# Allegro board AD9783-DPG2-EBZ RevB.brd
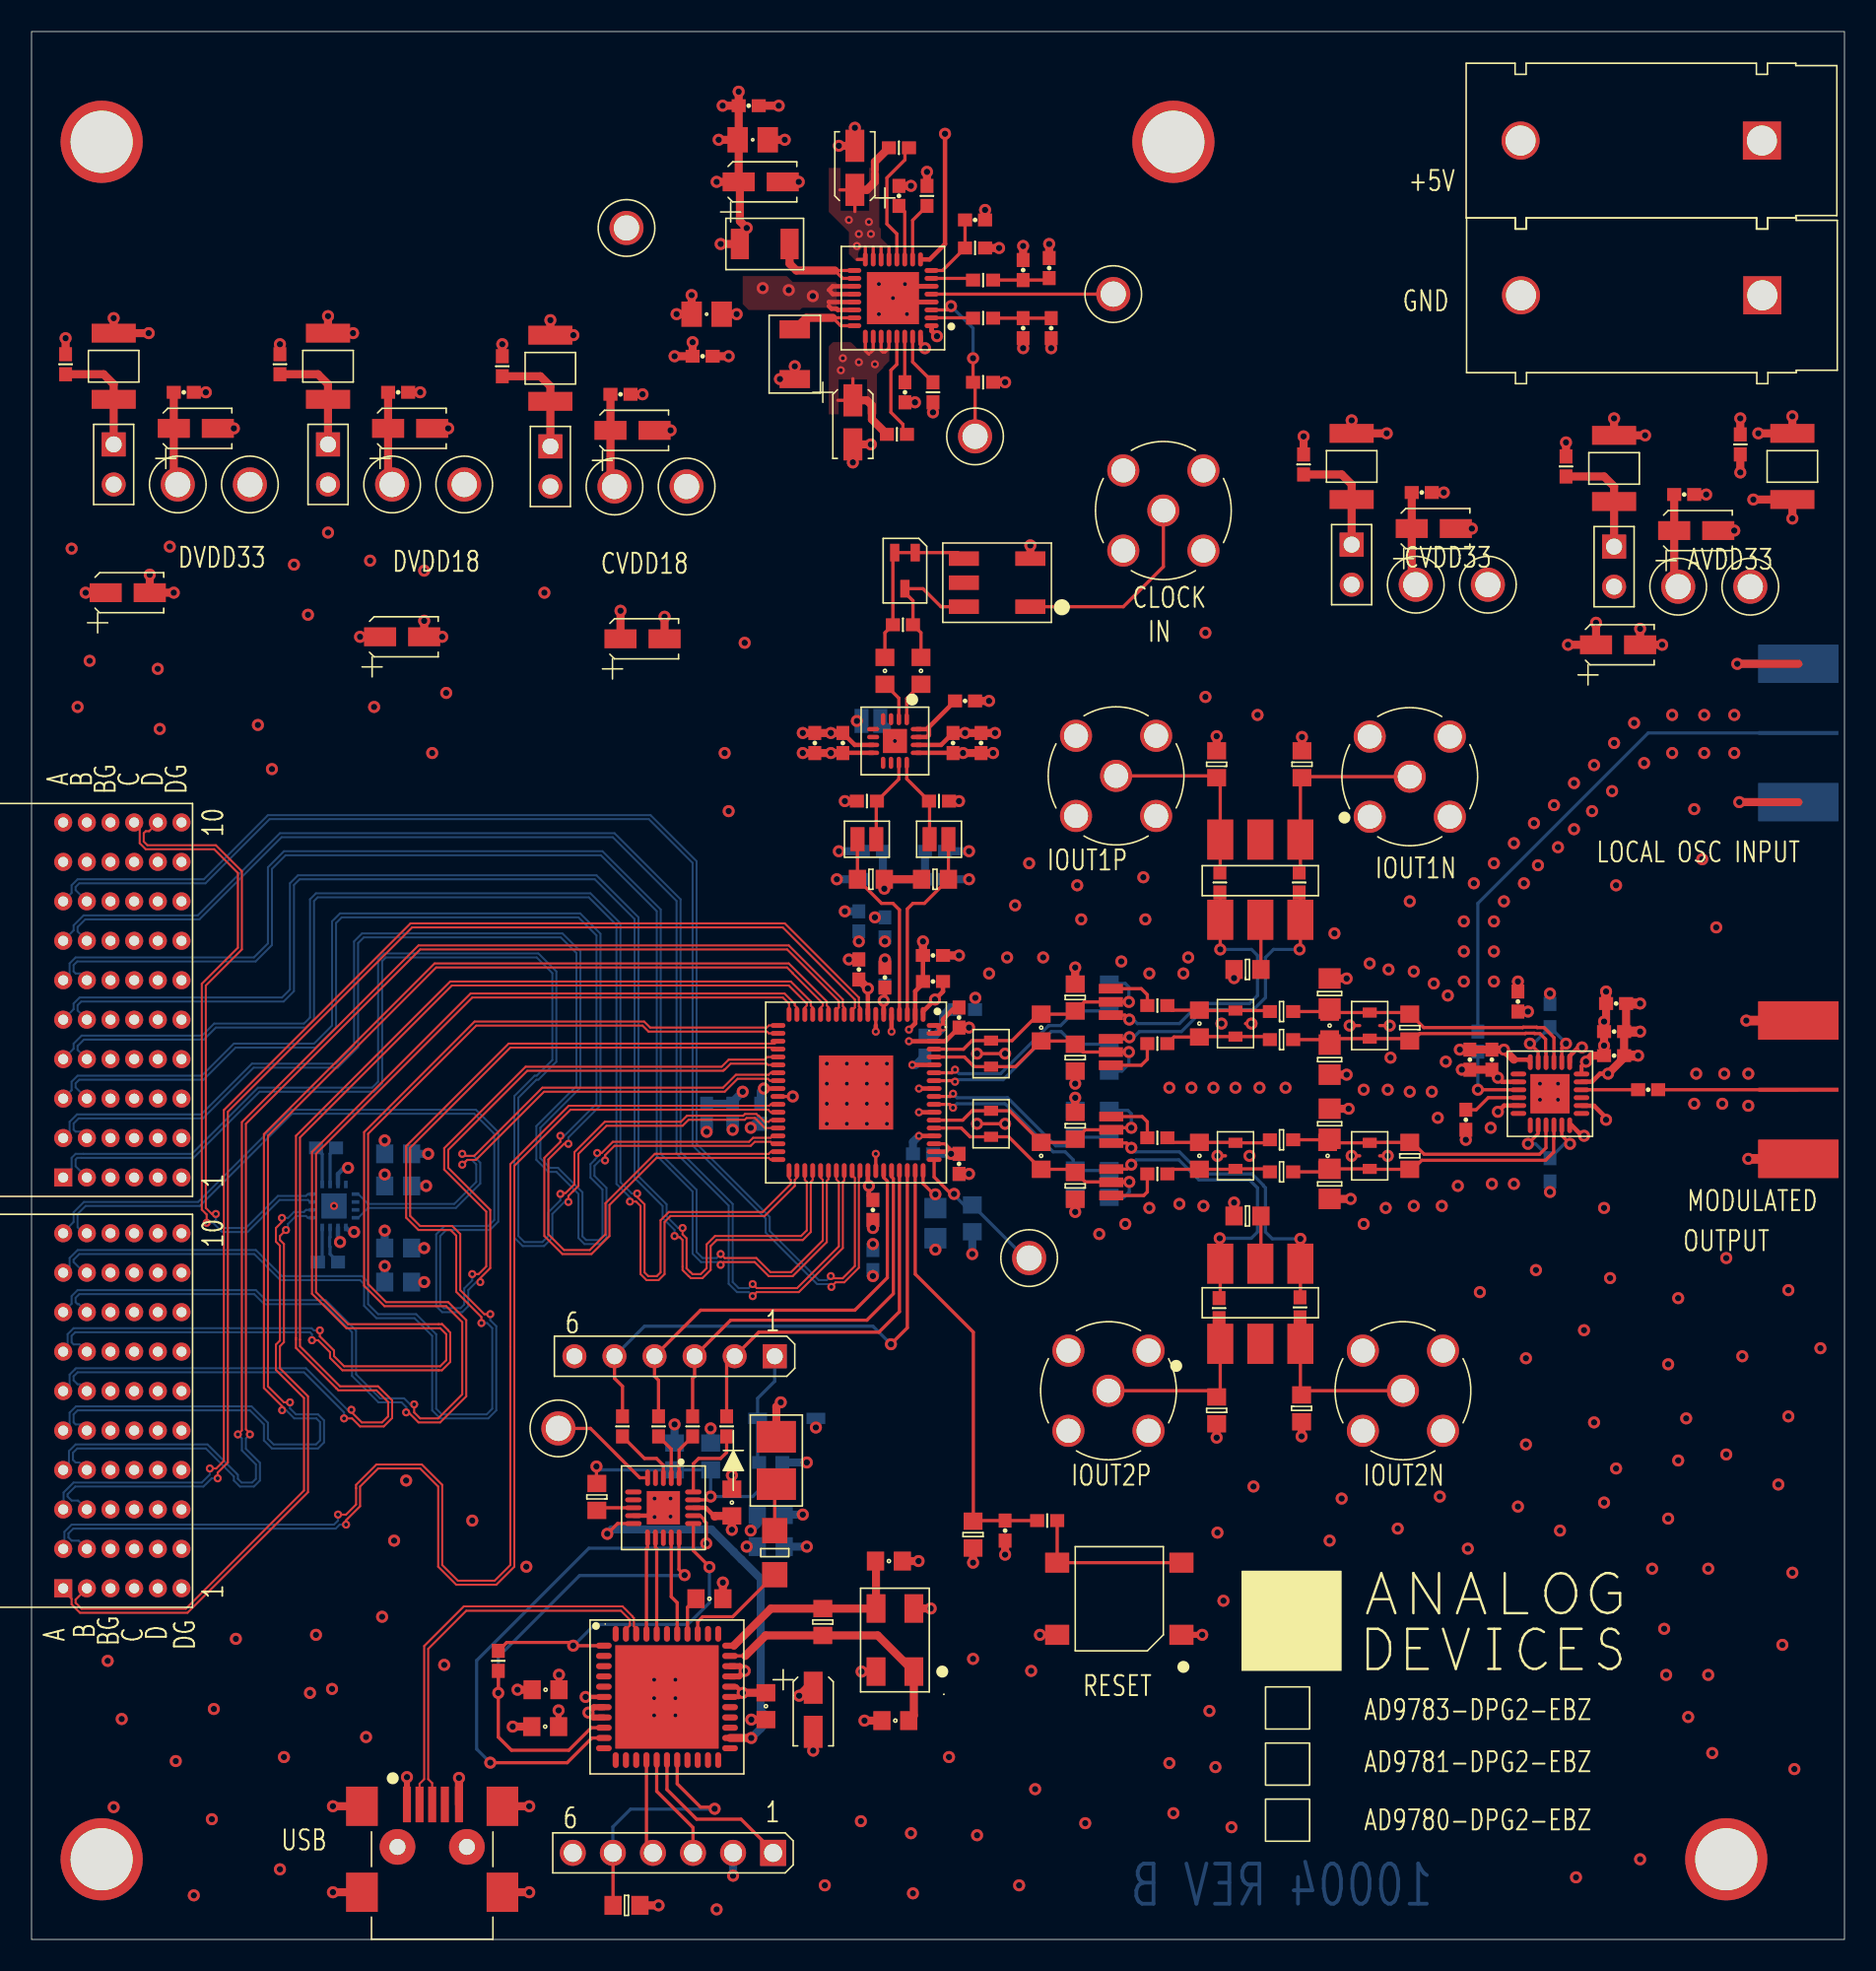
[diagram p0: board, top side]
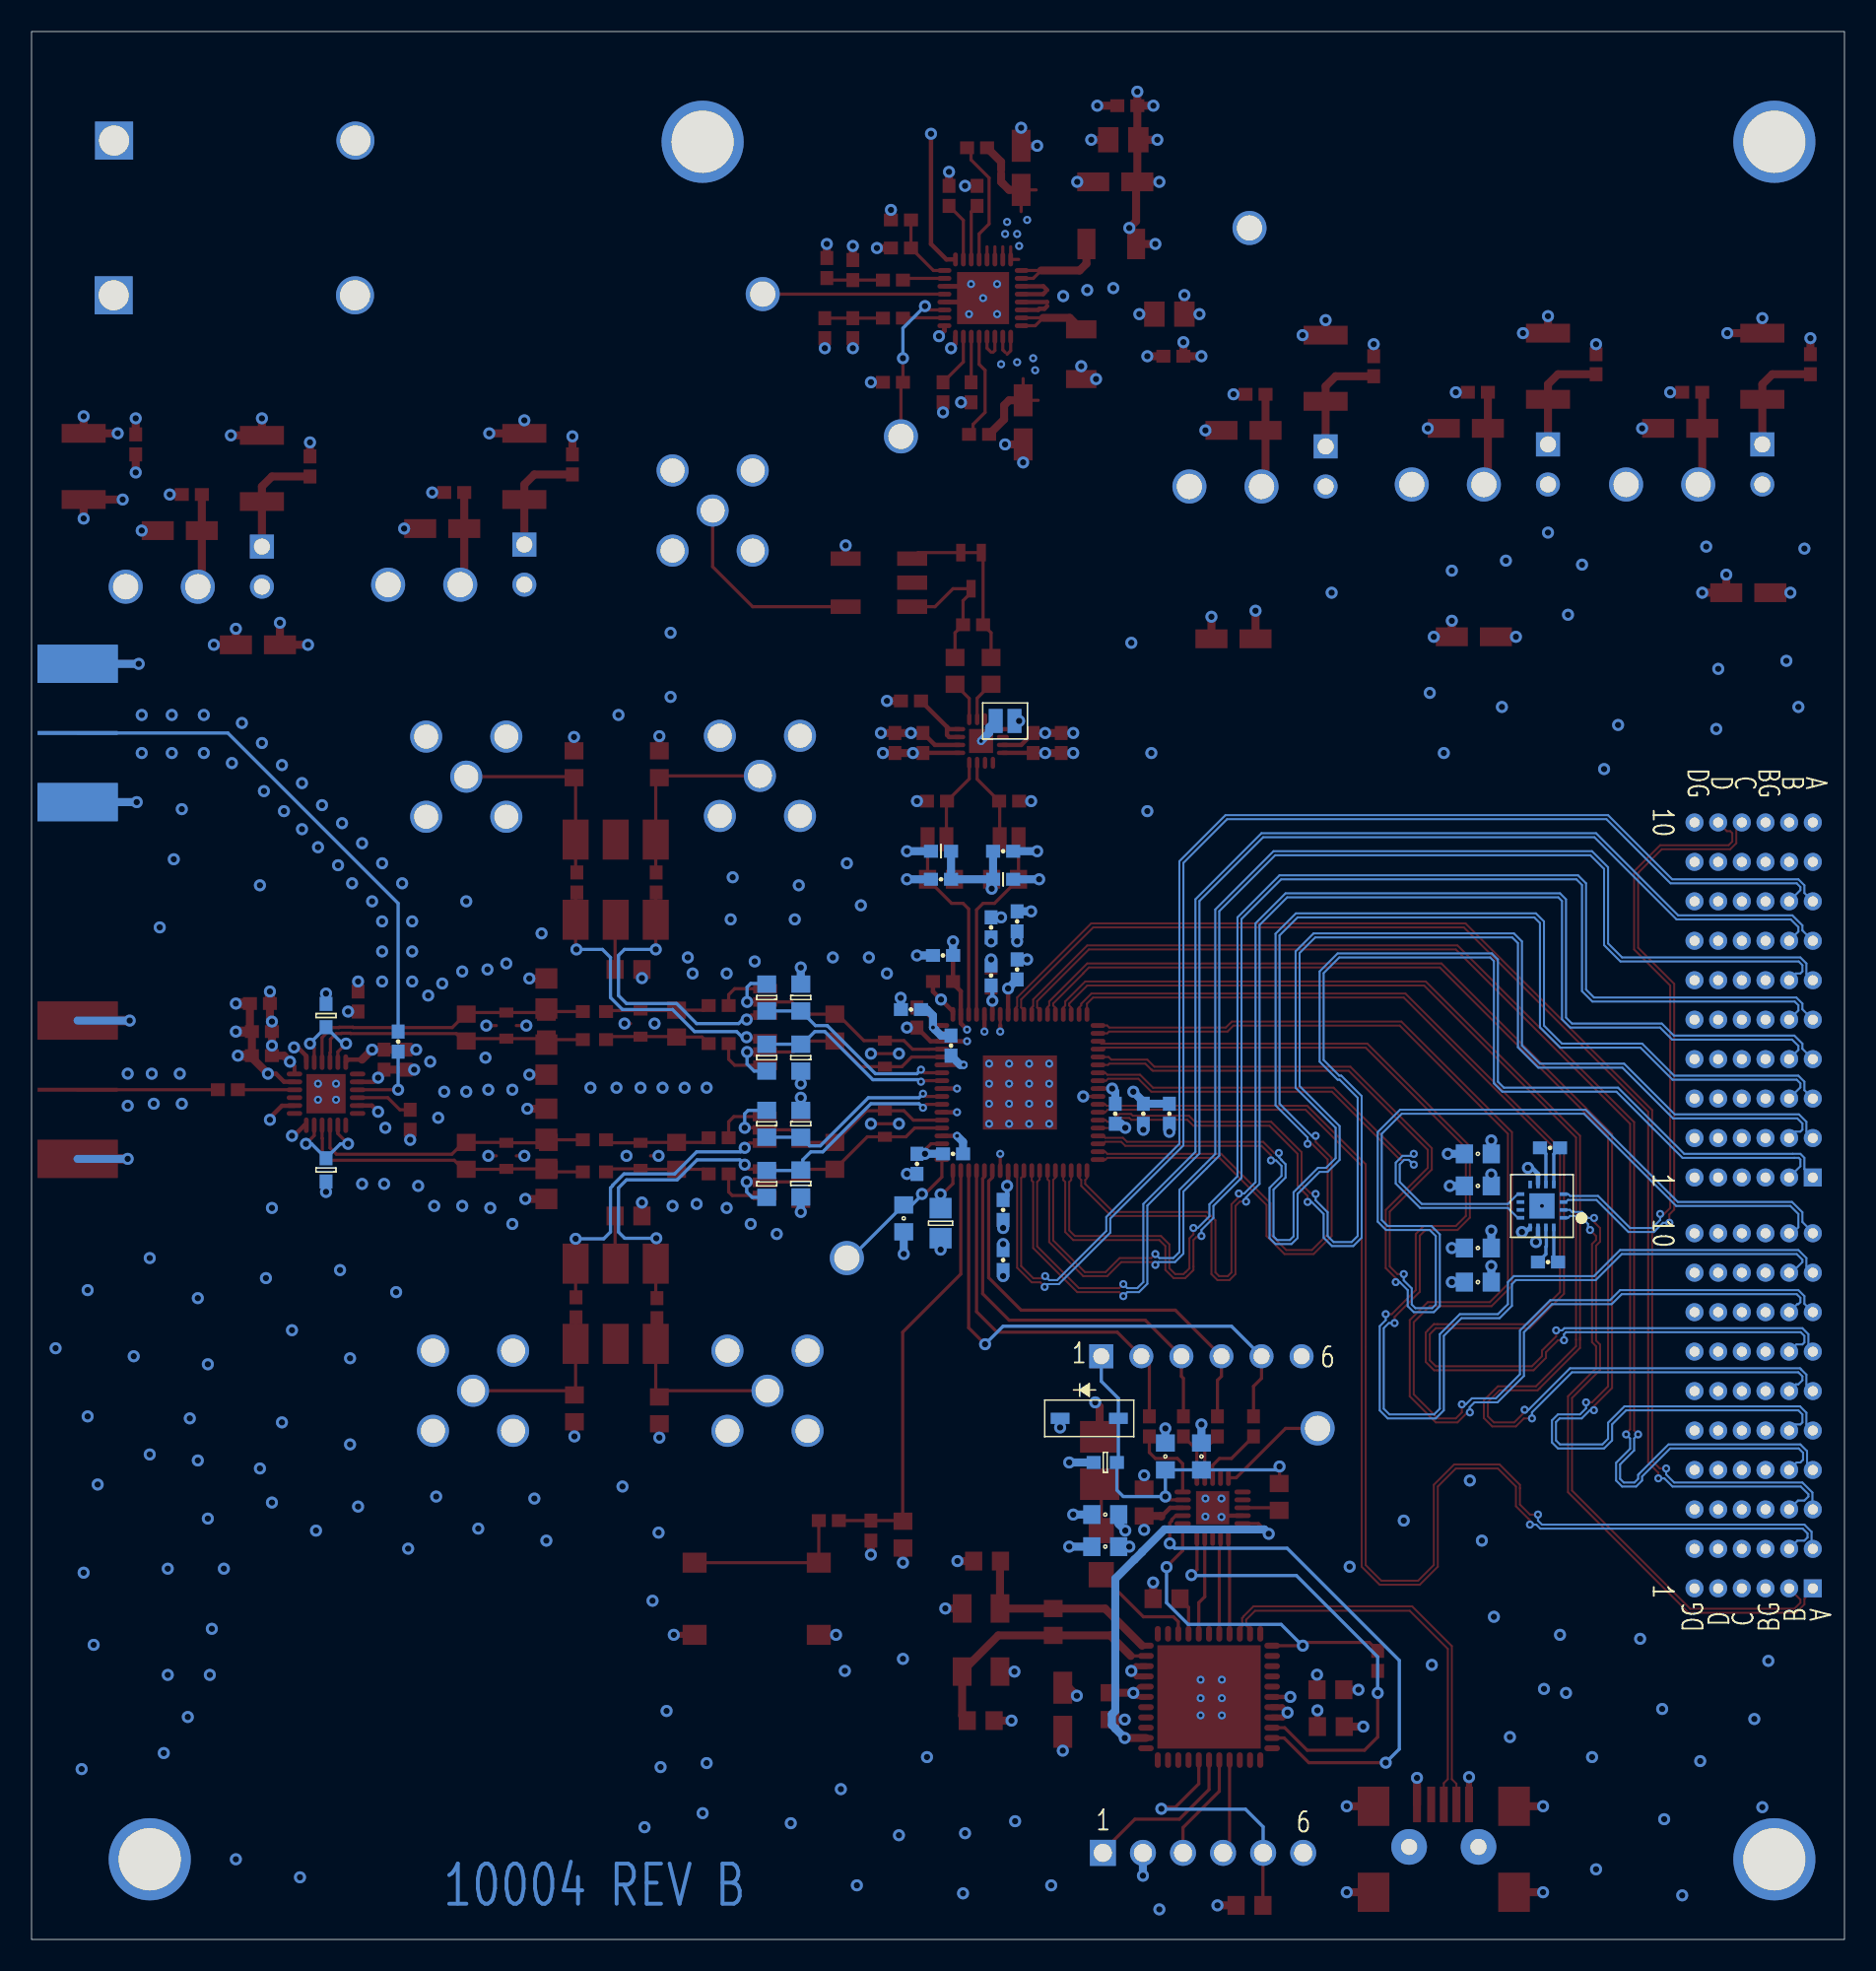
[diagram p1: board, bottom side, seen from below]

Outline 114.94 x 120.9 mm; copper layers: TOP, L2GND, L3PWR, L4PWR, L5GND, BOTTOM. Coordinates in mm from the lower left corner of the outline.
Outline path: 0,120.9 114.94,120.9 114.94,0 0,0 0,120.9

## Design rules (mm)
net group D0: nets D0N D0P
net group D1: nets D1N D1P
net group D2: nets D2N D2P
net group D3: nets D3N D3P
net group D4: nets D4N D4P
net group D5: nets D5N D5P
net group D6: nets D6N D6P
net group D7: nets D7N D7P
net group D8: nets D8N D8P
net group D9: nets D9N D9P
net group D10: nets D10N D10P
net group D11: nets D11N D11P
net group D12: nets D12N D12P
net group D13: nets D13N D13P
net group D14: nets D14N D14P
net group D15: nets D15N D15P
net group DCI: nets DCI_N DCI_P
net group DCO: nets DCO_N DCO_P
net group Q1: nets Q1_N Q1_P
net group Q2: nets Q2_N Q2_P
net group USB_D: nets USB_D+ USB_D-
net group PWR: nets AVDD33 CVDD18 CVDD33 DVDD18 DVDD33 USB_VCC

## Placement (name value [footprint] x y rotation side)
C1  1000PF  [C0402]  100.33 56.01 0 top
C2  10000PF  [C0603]  23.24 49.78 0 bottom
C3  0.1UF  [C0603]  23.24 47.75 0 bottom
C4  0.1UF  [C0603]  23.24 43.81 0 bottom
C5  1000PF  [C0402]  92.58 55.75 270 top
C6  10000PF  [C0603]  23.24 41.66 0 bottom
C7  22PF  [C0603-4P]  76.33 58.04 270 top
C8  10PF  [C0603-4P]  60.83 56.13 90 top
C9  10PF  [C0603-4P]  60.83 51.69 90 top
C10  22PF  [C0603-4P]  76.33 49.66 90 top
C13  1000PF  [C0402]  59.18 78.49 0 top
C14  .1UF  [C0306]  53.21 77.22 180 bottom
C15  .1UF  [C0402]  49.66 75.82 90 top
C16  1000PF  [C0402]  51.44 75.82 90 top
C17  1000PF  [C0402]  61.72 25.91 270 top
C18  0.1UF  [C0603]  56.39 80.39 270 top
C19  0.1UF  [C0603]  54.1 80.39 270 top
C20  .1UF  [C0306]  57.53 69.72 0 top
C21  .1UF  [C0306]  52.96 69.72 180 top
C22  1000PF  [C0402]  91.69 56.9 270 bottom
C23  .1UF  [C0402]  53.34 68.96 180 bottom
C24  100PF  [C0402]  57.28 67.18 0 bottom
C25  .1UF  [C0402]  52.45 64.52 90 bottom
C26  10PF  [C0603-4P]  84.84 57.91 270 top
C27  10PF  [C0603-4P]  84.84 49.66 90 top
C28  .1UF  [C0402]  57.15 62.36 180 bottom
C29  82PF  [C0603]  64.01 49.66 90 top
C30  82PF  [C0603]  64.01 57.78 270 top
C31  1UF  [C0402]  59.82 108.97 0 top
C32  0.01UF  [C0402]  55.37 98.04 270 top
C33  0.01UF  [C0402]  54.99 110.49 90 top
C34  22UF  [C3216]  52.2 112.27 90 top
C35  22UF  [C3216]  52.07 96.14 270 top
C36  1000PF  [C0402]  64.52 105.92 90 top
C37  100PF  [C0402]  62.86 105.79 90 top
C38  1000PF  [C0402]  62.86 102.11 270 top
C39  22UF  [C3216]  46.23 111.38 0 top
C40  1000PF  [C0402]  90.93 51.94 90 top
C41  100PF  [C0402]  64.64 102.11 270 top
C42  47UF  [C0805H60]  42.8 103 0 top
C43  47UF  [C0805H60]  45.72 114.05 0 top
C44  0.47UF  [C0402]  42.55 100.33 0 top
C45  0.47UF  [C0402]  45.47 116.2 0 top
C46  22UF  [C3216]  105.54 89.28 0 top
C47  22UF  [C3216]  10.41 95.76 0 top
C48  10PF  [C0603]  74.04 58.04 90 top
C49  22UF  [C3216]  88.9 89.41 0 top
C50  22UF  [C3216]  24 95.76 0 top
C51  22UF  [C3216]  38.1 95.63 0 top
C52  0.1UF  [C0402]  104.78 91.57 0 top
C53  0.1UF  [C0402]  9.65 98.04 0 top
C54  0.1UF  [C0402]  88.14 91.69 0 top
C55  0.1UF  [C0402]  23.24 98.04 0 top
C56  0.1UF  [C0402]  37.34 97.92 0 top
C63  .1UF  [C0402]  42.8 52.32 270 bottom
C66  1000PF  [C0402]  44.45 52.32 270 bottom
C67  1000PF  [C0402]  53.34 46.23 270 bottom
C68  1000PF  [C0402]  57.15 62.36 180 top
C69  100PF  [C0402]  57.15 60.71 180 top
C70  100PF  [C0402]  52.45 61.47 90 top
C71  100PF  [C0402]  46.23 52.32 270 bottom
C72  10UF  [C3216]  6.1 85.34 0 top
C73  10UF  [C3216]  23.49 82.55 0 top
C77  .1UF  [C0402]  53.34 43.05 270 bottom
C83  100PF  [C0402]  54.1 60.96 90 top
C84  .1UF  [C0402]  60.2 75.82 90 top
C85  .1UF  [C0402]  56.64 56.64 270 bottom
C86  .1UF  [C0402]  56.52 49.78 180 bottom
C87  1000PF  [C0402]  59.18 58.93 0 bottom
C88  1000PF  [C0402]  58.8 49.15 270 bottom
C89  100PF  [C0402]  58.8 58.42 270 top
C90  100PF  [C0402]  58.8 49.15 270 top
C91  0.1UF  [C0603]  59.64 45.69 90 bottom
C92  10UF  [C3216]  100.58 82.04 0 top
C94  1000PF  [C0402]  102.49 53.85 0 top
C95  6.0PF  [C0603]  82.3 57.91 90 top
C98  10PF  [C0603]  74.04 49.66 270 top
C100  6.0PF  [C0603]  82.17 49.66 270 top
C102  10UF  [C3216]  38.73 82.42 0 top
C103  .1UF  [C0402]  54.1 64.13 90 bottom
C104  1000PF  [C0402]  52.45 61.47 90 bottom
C105  1000PF  [C0402]  54.1 61.09 90 bottom
C106  100PF  [C0402]  53.34 46.23 270 top
C107  1000PF  [C0402]  58.42 75.82 90 top
C108  0.1UF  [C0402]  100.33 57.53 0 top
C132  0.1UF  [C0402]  91.19 55.75 270 top
C200  .01UF  [C0402]  94.23 59.44 90 top
C230  .01UF  [C0402]  100.46 59.31 0 top
CR4  HSMS-281C-BLKG  [SC-70-3]  55.37 86.74 180 top
E1  115OHMS  [INDL177W126H71]  100.33 93.22 270 top
E2  115OHMS  [INDL177W126H71]  5.21 99.69 270 top
E3  115OHMS  [INDL177W126H71]  83.69 93.34 270 top
E4  115OHMS  [INDL177W126H71]  18.8 99.69 270 top
E5  115OHMS  [INDL177W126H71]  32.89 99.57 270 top
E6  115OHMS  [INDL177W126H71]  111.63 93.34 270 top
J1  JOHNSON142-0701-201  [CNJOHNSON142-0701-201]  71.75 90.55 0 top
J2  JOHNSON142-0701-851  [CNJOHNSON142-0701-851]  112.01 76.45 0 bottom
J5  JOHNSON142-0701-201  [CNJOHNSON142-0701-201]  68.76 73.74 0 top
J6  JOHNSON142-0701-851  [CNJOHNSON142-0701-851]  112.01 53.85 0 top
J7  JOHNSON142-0701-201  [CNJOHNSON142-0701-201]  87.38 73.69 0 top
J8  JOHNSON142-0701-201  [CNJOHNSON142-0701-201]  86.94 34.77 0 top
J9  JOHNSON142-0701-201  [CNJOHNSON142-0701-201]  68.28 34.77 0 top
J17  1469028-1  [CNTYCO1469028-1]  2.01 22.25 90 top
J18  1469028-1  [CNTYCO1469028-1]  2.01 48.29 90 top
JP1  BERG69157-102  [CNBERG69157-102]  100.33 88.27 270 top
JP2  BERG69157-102  [CNBERG69157-102]  5.21 94.74 270 top
JP3  BERG69157-102  [CNBERG69157-102]  83.69 88.39 270 top
JP4  3PIN_SOLDER_JUMPER  [JPRSLD03]  68.43 59.41 270 top
JP5  3PIN_SOLDER_JUMPER  [JPRSLD03]  68.43 56.24 90 top
JP6  3PIN_SOLDER_JUMPER  [JPRSLD03]  68.45 47.98 90 top
JP7  3PIN_SOLDER_JUMPER  [JPRSLD03]  68.45 51.31 270 top
JP8  BERG69157-102  [CNBERG69157-102]  18.8 94.74 270 top
JP9  BERG69157-102  [CNBERG69157-102]  32.89 94.61 270 top
JP10  JPR0402  [R0402]  97.28 93.34 270 top
JP11  JPR0402  [R0402]  2.16 99.82 270 top
JP12  JPR0402  [R0402]  80.64 93.47 270 top
JP13  JPR0402  [R0402]  15.75 99.82 270 top
JP14  JPR0402  [R0402]  29.84 99.69 270 top
JP15  JPR0402  [R0402]  108.33 94.74 270 top
JP21  JPR0402  [R0402]  75.34 66.98 90 top
JP22  JPR0402  [R0402]  80.37 66.98 90 top
JP23  JPR0402  [R0402]  80.42 40.06 270 top
JP24  JPR0402  [R0402]  75.29 40 270 top
L1  TBD0603  [L0603]  96.27 48.77 90 bottom
L2  TBD0603  [L0603]  96.27 58.55 270 bottom
L4  3.3UH  [NL1210]  48.39 100.46 270 top
L5  56NH  [L0603]  79.25 58.8 0 top
L6  56NH  [L0603]  79.25 57.02 0 top
L7  56NH  [L0603]  79.25 48.64 0 top
L8  33NH  [L0402]  71.37 48.51 0 top
L9  33NH  [L0402]  71.37 50.8 0 top
L10  33NH  [L0402]  71.37 59.18 0 top
L11  33NH  [L0402]  71.37 56.77 0 top
L12  3.3UH  [NL1210]  46.48 107.44 180 top
L13  56NH  [L0603]  79.25 50.67 0 top
NOREF  -  [unnamed]  4.45 5.08 0 top
NOREF#2  -  [unnamed]  72.39 113.92 0 top
NOREF#3  -  [unnamed]  107.44 5.08 0 top
NOREF#4  -  [#2]  238.76 146.05 0 top
NOREF#5  -  [#2]  209.55 174.88 0 top
NOREF#6  -  [#2]  0 0 90 top
NOREF#7  -  [#2]  -6.35 -6.35 0 top
NOREF#8  -  [#2]  0 0 0 top
NOREF#9  -  [#2]  114.94 120.9 180 top
NOREF#10  -  [#2]  235.71 -36.96 0 top
NOREF#11  -  [#2]  114.94 0 90 top
NOREF#12  -  [#2]  0 120.9 270 top
NOREF#13  -  [#2]  -105.41 -220.85 0 top
NOREF#14  -  [#2]  0 0 0 top
NOREF#15  -  [#2]  121.28 127.25 0 top
NOREF#16  -  [#2]  54.36 153.67 0 top
NOREF#17  -  [#2]  -6.35 127.25 0 top
NOREF#18  -  [#2]  0 0 90 top
NOREF#19  -  [unnamed]  4.45 113.92 0 top
NOREF#20  -  [#2]  0 0 0 top
NOREF#21  -  [#2]  76.71 17.02 180 bottom
P5  571-0500  [CNDELTRON-571]  109.7 114 180 top
P6  571-0100  [CNDELTRON-571]  109.73 104.19 180 top
R1  100  [R0402]  18.8 42.93 180 bottom
R2  49.9  [R0805]  82.3 59.94 270 top
R3  49.9  [R0805]  82.3 55.75 270 top
R4  49.9  [R0805]  82.3 47.88 90 top
R5  49.9  [R0805]  82.3 51.69 90 top
R6  49.9  [R0402]  55.24 83.31 180 top
R7  100  [R0402]  64.39 26.54 180 top
R8  200  [R0402]  57.53 72.14 0 top
R9  200  [R0402]  52.96 72.14 0 top
R10  1K  [R0402]  57.28 68.96 180 bottom
R11  287  [R0402]  53.34 67.18 180 bottom
R12  49.9  [R0603]  57.28 67.18 0 top
R13  49.9  [R0603]  53.21 67.18 0 top
R14  0  [R0603]  77.09 61.47 0 top
R15  0  [R0603]  77.09 45.85 0 top
R16  8.2K  [R0402]  60.32 98.68 0 top
R17  10  [R0402]  59.82 107.19 180 top
R18  47K  [R0402]  57.15 98.04 90 top
R19  15K  [R0402]  56.77 110.49 270 top
R20  100K  [R0402]  54.99 113.54 0 top
R21  10K  [R0805]  57.3 45.39 90 bottom
R22  100K  [R0402]  54.86 95.38 0 top
R23  137  [R0603]  87.38 49.66 270 top
R24  137  [R0603]  87.38 57.78 90 top
R25  22.1K  [R0402]  60.32 105.16 0 top
R26  499  [R0603]  68.33 55.88 270 bottom
R27  499  [R0603]  68.33 51.69 90 bottom
R28  499  [R0603]  68.33 59.69 90 bottom
R29  499  [R0603]  68.33 47.88 270 bottom
R30  100  [R0402]  18.67 50.16 180 bottom
R31  10K  [R0603]  59.69 25.65 90 top
R32  499  [R0603]  66.17 55.88 90 bottom
R33  499  [R0603]  66.17 51.69 270 bottom
R34  49.9  [R0603]  66.17 59.69 270 top
R35  49.9  [R0603]  66.17 47.75 90 top
R36  49.9  [R0603]  66.17 55.88 90 top
R37  49.9  [R0603]  66.17 51.56 270 top
R38  TBD0603  [R0603]  75.13 74.47 90 top
R39  0  [R0603]  80.54 74.47 270 top
R40  TBD0603  [R0603]  80.52 33.66 270 top
R41  0  [R0603]  75.13 33.53 90 top
R42  27K  [R0402]  60.32 102.74 0 top
R43  499  [R0603]  66.17 59.69 270 bottom
R44  499  [R0603]  66.17 47.9 90 bottom
S2  B3S1000  [SWB3S1000]  68.96 21.59 0 top
T2  MABACT0043  [TSMTYCOSM138-2]  61.21 85.98 90 top
T7  ADT2-1T-1P+  [MINICD542]  77.9 67.16 180 top
T8  ADT2-1T-1P+  [MINICD542]  77.9 40.28 0 top
TP1  WHT  [CNLOOPTP]  59.82 95.25 0 top
TP2  WHT  [CNLOOPTP]  68.58 104.27 0 top
TP3  RED  [CNLOOPTP]  104.39 85.72 0 top
TP4  BLK  [CNLOOPTP]  108.97 85.72 0 top
TP5  RED  [CNLOOPTP]  9.27 92.2 0 top
TP6  BLK  [CNLOOPTP]  13.84 92.2 0 top
TP7  RED  [CNLOOPTP]  87.76 85.85 0 top
TP8  BLK  [CNLOOPTP]  92.33 85.85 0 top
TP9  RED  [CNLOOPTP]  22.86 92.2 0 top
TP10  BLK  [CNLOOPTP]  27.43 92.2 0 top
TP11  RED  [CNLOOPTP]  36.96 92.08 0 top
TP12  BLK  [CNLOOPTP]  41.53 92.08 0 top
TP13  BLK  [CNLOOPTP]  37.72 108.46 0 top
TP14  WHT  [CNLOOPTP]  33.4 32.38 0 top
TP16  WHT  [CNLOOPTP]  63.25 43.18 0 top
U1  ADCLK905BCPZ-WP  [LFCSP16-3X3-PAD1_5X1_5]  54.74 75.95 180 top
U2  AD9783BCPZ  [QFN72_10X10_PAD4_7X4_7]  52.27 53.67 180 top
U3  SY89833LMG  [MLF16_3X3_PAD1_6X1_6]  19.18 46.48 90 bottom
U4  ADL5375-05ACPZ-R7  [QFN24_4X4_PAD2_5X2_5]  96.27 53.59 270 top
VR1  ADP2114_PRELIM  [QFN32_5X5_PAD3_3X3_3]  54.61 104.01 90 top
XC1  10PF  [C0603]  54.76 13.87 0 top
XC2  10PF  [C0603]  54.36 23.98 180 top
XC3  .47UF  [C0603]  42.98 21.59 180 top
XC4  10UF  [C3216]  49.56 14.55 270 top
XC5  0.1UF  [C0603]  46.56 14.78 90 top
XC6  0.1UF  [C0603]  32.59 15.82 0 top
XC7  0.1UF  [C0603]  32.56 13.49 0 top
XC8  0.1UF  [C0603]  44.4 27.69 270 top
XC11  0.1UF  [C0603]  43.05 30.61 270 bottom
XC12  1UF  [C0603]  40.77 30.61 90 bottom
XC57  1UF  [C0603]  46.86 24.89 0 bottom
XC58  0.1UF  [C0603]  46.86 26.92 180 bottom
XCR1  BAT46W-7-F  [SOD123-3]  47.88 33.02 180 bottom
XD1  CCL-CRS10G (GREEN)  [LEDSML118W100H48]  47.22 30.35 270 top
XJP1  JPR0402  [R0402]  41.91 32.51 270 top
XJP3  JPR0402  [R0402]  39.75 32.51 270 top
XJP4  JPR0402  [R0402]  37.47 32.51 270 top
XJP5  JPR0402  [R0402]  44.07 32.51 270 top
XL3  TBD0603  [L0603]  46.86 30.23 180 bottom
XP1  SAMTECTSW10608GS6PIN  [CNBERG1X6H205LD36]  47.02 5.49 180 top
XP2  MUSB-05-F-AB-SM-A-R  [CNSAM-MUSB-05-F-AB-SM-A-R]  25.4 5.72 0 top
XP3  SAMTECSSW10601GS  [CNBERGF1X6H330LD31]  47.12 36.96 180 top
XR1  10K  [R0603]  35.84 28.04 90 top
XR2  1K  [R0603]  37.72 2.16 180 top
XR3  1M  [R0603]  50.16 20.12 90 top
XR4  200  [R1206]  47.12 24.51 90 top
XR6  0  [R0402]  29.59 17.65 270 top
XU1  ADG3308BCPZ  [QFN20_4X4_PAD2_1X2_1]  40.06 27.36 180 top
XU2  PIC18F4550-I/ML  [QFN44_8X8_PAD6_55X6_55]  40.28 15.37 270 top
XY1  20.000MHZ  [XTALABM3B]  54.74 18.97 90 top

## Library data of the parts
C1 C5 C13 C16 C17 C22 C36 C38 C40 C66-C68 C87 C88 C94 C104 C105 C107 = CAP: Tolerance: 10; User Part Number: UPN; part number: CAP_SM-1000PF,25V,10,E000257,C0402; tolerance: 10
C2 C6 = CAP: User Part Number: UPN; Tolerance: 10; part number: CAP_SM-10000PF,50V,10,E000307,C0603; tolerance: 10
C3 C4 = CAP: User Part Number: UPN; Tolerance: 10; part number: CAP_SM-0.1UF,25V,10,E007204,C0603; tolerance: 10
C7 C10 = CAP4P_V2: Tolerance: 20; User Part Number: UPN; part number: CAP4P_V2_SM-22PF,100V,20,E011926,C0603-4P; tolerance: 20
C8 C9 C26 C27 = CAP4P_V2: Tolerance: 20; User Part Number: UPN; part number: CAP4P_V2_SM-10PF,100V,20,E011927,C0603-4P; tolerance: 20
C14 C20 C21 = CAP: Tolerance: 10; User Part Number: UPN; part number: CAP_SM-.1UF,10V,10,E000379,C0306; tolerance: 10
C15 C23 C25 C28 C63 C77 C84-C86 C103 = CAP: Tolerance: 60; User Part Number: UPN; part number: CAP_SM-.1UF,16V,60,E000274,C0402; tolerance: 60
C18 C19 = CAP: Tolerance: 10; User Part Number: UPN; part number: CAP_SM-0.1UF,16V,10,E000312,C0603; tolerance: 10
C24 C69-C71 C83 C89 C90 C106 = CAP: Tolerance: 10; User Part Number: UPN; part number: CAP_SM-100PF,50V,10,E000256,C0402; tolerance: 10
C29 C30 = CAP: Tolerance: 5; User Part Number: UPN; part number: CAP_SM-82PF,50V,5,E000414,C0603; tolerance: 5
C31 = CAP: Tolerance: 10; User Part Number: UPN; part number: CAP_SM-1UF,6.3V,10,E007449,C0402; tolerance: 10
C32 C33 = CAP: Tolerance: 10; User Part Number: UPN; part number: CAP_SM-0.01UF,25V,10,E007203,C0402; tolerance: 10
C34 C35 C39 C47 = CAPP: Tolerance: 10; User Part Number: UPN; part number: CAPP_SM-22UF,6.3V,10,E000683,C3216; tolerance: 10
C37 C41 = CAP: Tolerance: 5; User Part Number: UPN; part number: CAP_SM-100PF,50V,5,E007896,C0402; tolerance: 5
C42 C43 = CAP: Tolerance: 10; User Part Number: UPN; part number: CAP_SM-47UF,6.3V,10,E008247,C0805H60; tolerance: 10
C44 C45 = CAP: Tolerance: 10; User Part Number: UPN; part number: CAP_SM-0.47UF,10V,10,E007611,C0402; tolerance: 10
C46 C49-C51 = CAPP: User Part Number: UPN; Tolerance: 10; part number: CAPP_SM-22UF,6.3V,10,E000683,C3216; tolerance: 10
C48 C98 XC1 XC2 = CAP: Tolerance: 5; User Part Number: UPN; part number: CAP_SM-10PF,50V,5,E000104,C0603; tolerance: 5
C52 C54-C56 C108 C132 = CAP: Tolerance: 10; User Part Number: UPN; part number: CAP_SM-0.1UF,16V,10,E006560,C0402; tolerance: 10
C53 = CAP: User Part Number: UPN; Tolerance: 10; part number: CAP_SM-0.1UF,16V,10,E006560,C0402; tolerance: 10
C72 C73 C92 C102 = CAPP: Tolerance: 10; User Part Number: UPN; part number: CAPP_SM-10UF,6.3V,10,E000634,C3216; tolerance: 10
C91 = CAP: Tolerance: 10; User Part Number: UPN; part number: CAP_SM-0.1UF,25V,10,E000311,C0603; tolerance: 10
C95 C100 = CAP: Tolerance: 0.5PF; User Part Number: UPN; part number: CAP_SM-6.0PF,50V,0.5PF,E000321,C0603; tolerance: 0.5PF
C200 C230 = CAP: Tolerance: 10; User Part Number: UPN; part number: CAP_SM-.01UF,16V,10,E000258,C0402; tolerance: 10
CR4 = DIOHSMS28X2: Tolerance: N/A; User Part Number: UPN; part number: DIOHSMS28X2_SM-HSMS-281C-BLKG,0.4V,N/A,E007526,SC-70-3; tolerance: N/A
E1 E3-E6 = FERRITE: Tolerance: N/A; User Part Number: UPN; part number: FERRITE_SM-115OHMS,N/A,E006418,INDL177W126H71; tolerance: N/A
E2 = FERRITE: User Part Number: UPN; Tolerance: N/A; part number: FERRITE_SM-115OHMS,N/A,E006418,INDL177W126H71; tolerance: N/A
J1 J5 J7-J9 = CNBNC5P: User Part Number: UPN; part number: CNBNC5P_TH-JOHNSON142-0701-201,E000916,CNJOHNSON142-0701-201
J2 J6 = CNBNC5P: User Part Number: UPN; part number: CNBNC5P_SM-JOHNSON142-0701-851,E000923,CNJOHNSON142-0701-851
J17 J18 = CNTYCO60P: User Part Number: UPN; part number: CNTYCO60P_TH-1469028-1,E006333,CNTYCO1469028-1
JP1-JP3 JP8 JP9 = CNJMPRSHRT: User Part Number: UPN; part number: CNJMPRSHRT_TH-BERG69157-102,E000942,CNBERG69157-102
JP4-JP7 = NC3P_JMPR: part number: NC3P_JMPR_SM-3PIN_SOLDER_JUMPER,E005606,JPRSLD03
JP10-JP15 XJP1 XJP3-XJP5 = NC2P_JMPRSHRT: User Part Number: UPN; part number: NC2P_JMPRSHRT_SM-JPR0402,E005614,R0402
JP21-JP24 = NC2P_JMPROPEN: User Part Number: UPN; part number: NC2P_JMPROPEN_SM-JPR0402,E005614,R0402
L1 L2 XL3 = IND: User Part Number: UPN; part number: IND_SM-TBD0603,TBD0603,E002419,L0603
L4 L12 = IND: Tolerance: 5; User Part Number: UPN; part number: IND_SM-3.3UH,5,E002407,NL1210; tolerance: 5
L5-L7 L13 = IND: Tolerance: 2; User Part Number: UPN; part number: IND_SM-56NH,2,E002368,L0603; tolerance: 2
L8-L11 = IND: Tolerance: 5; User Part Number: UPN; part number: IND_SM-33NH,5,E006368,L0402; tolerance: 5
P5 = CN2P: User Part Number: UPN; part number: CN2P_TH-571-0500,E007692,CNDELTRON-571
P6 = CN2P: User Part Number: UPN; part number: CN2P_TH-571-0100,E007691,CNDELTRON-571
R1 R30 = RES: User Part Number: UPN; Tolerance: 1; part number: RES_SM-100,1/16W,1,E003760,R0402; tolerance: 1
R2-R5 = RES: Tolerance: 1; User Part Number: UPN; part number: RES_SM-49.9,1/8W,1,E003412,R0805; tolerance: 1
R6 = RES: Tolerance: 1; User Part Number: UPN; part number: RES_SM-49.9,1/16W,1,E003750,R0402; tolerance: 1
R7 = RES: Tolerance: 1; User Part Number: UPN; part number: RES_SM-100,1/16W,1,E003760,R0402; tolerance: 1
R8 R9 = RES: Tolerance: 1; User Part Number: UPN; part number: RES_SM-200,1/16W,1,E003753,R0402; tolerance: 1
R10 = RES: Tolerance: 0.1; User Part Number: UPN; part number: RES_SM-1K,1/16W,0.1,E005978,R0402; tolerance: 0.1
R11 = RES: Tolerance: 1; User Part Number: UPN; part number: RES_SM-287,1/16W,1,E008040,R0402; tolerance: 1
R12 R13 R34 R36 R37 = RES: Tolerance: 1; User Part Number: UPN; part number: RES_SM-49.9,1/10W,1,E003673,R0603; tolerance: 1
R14 R15 R39 = RES: Tolerance: 5; User Part Number: UPN; part number: RES_SM-0,1/10W,5,E006826,R0603; tolerance: 5
R16 = RES: Tolerance: 5; User Part Number: UPN; part number: RES_SM-8.2K,1/16W,5,E007570,R0402; tolerance: 5
R17 = RES: Tolerance: 1; User Part Number: UPN; part number: RES_SM-10,1/16W,1,E003768,R0402; tolerance: 1
R18 = RES: Tolerance: 1; User Part Number: UPN; part number: RES_SM-47K,1/16W,1,E008189,R0402; tolerance: 1
R19 = RES: Tolerance: 1; User Part Number: UPN; part number: RES_SM-15K,1/16W,1,E007441,R0402; tolerance: 1
R20 R22 = RES: Tolerance: 1; User Part Number: UPN; part number: RES_SM-100K,1/16W,1,E003796,R0402; tolerance: 1
R21 = RES: Tolerance: 0.1; User Part Number: UPN; part number: RES_SM-10K,1/10W,0.1,E003806,R0805; tolerance: 0.1
R23 R24 = RES: Tolerance: 1; User Part Number: UPN; part number: RES_SM-137,1/10W,1,E003724,R0603; tolerance: 1
R25 = RES: Tolerance: 1; User Part Number: UPN; part number: RES_SM-22.1K,1/16W,1,E007152,R0402; tolerance: 1
R26 R28 = RES: Tolerance: 0.1; User Part Number: UPN; part number: RES_SM-499,1/10W,0.1,E006675,R0603; tolerance: 0.1
R27 R29 = RES: User Part Number: UPN; Tolerance: 0.1; part number: RES_SM-499,1/10W,0.1,E006675,R0603; tolerance: 0.1
R31 XR1 = RES: Tolerance: 1; User Part Number: UPN; part number: RES_SM-10K,1/10W,1,E003671,R0603; tolerance: 1
R32 R43 = RES: Tolerance: 1; User Part Number: UPN; part number: RES_SM-499,1/10W,1,E003667,R0603; tolerance: 1
R33 R44 = RES: User Part Number: UPN; Tolerance: 1; part number: RES_SM-499,1/10W,1,E003667,R0603; tolerance: 1
R35 = RES: User Part Number: UPN; Tolerance: 1; part number: RES_SM-49.9,1/10W,1,E003673,R0603; tolerance: 1
R38 R40 = RES: User Part Number: UPN; part number: RES_SM-TBD0603,TBD0603,TBD0603,E004050,R0603
R41 = RES: User Part Number: UPN; Tolerance: 5; part number: RES_SM-0,1/10W,5,E006826,R0603; tolerance: 5
R42 = RES: Tolerance: 1; User Part Number: UPN; part number: RES_SM-27K,1/16W,1,E007442,R0402; tolerance: 1
S2 = SWSPST4PIN: User Part Number: UPN; part number: SWSPST4PIN_SM-B3S1000,E004572,SWB3S1000
T2 = XFMRMABACT0043: User Part Number: UPN; part number: XFMRMABACT0043_SM-MABACT0043,E010289,TSMTYCOSM138-2
T7 T8 = XFMRMCCD542KS: User Part Number: UPN; part number: XFMRMCCD542KS_SM-ADT2-1T-1P+,E007172,MINICD542
TP1 TP2 TP14 TP16 = CNTP1P: User Part Number: UPN; part number: CNTP1P_TH-WHT,E000946,CNLOOPTP
TP3 TP5 TP7 TP9 TP11 = CNTP1P: User Part Number: UPN; part number: CNTP1P_TH-RED,E000947,CNLOOPTP
TP4 TP6 TP8 TP10 TP12 TP13 = CNTP1P: User Part Number: UPN; part number: CNTP1P_TH-BLK,E000948,CNLOOPTP
U1 = ADCLK905: User Part Number: UPN; part number: ADCLK905_SM-ADCLK905BCPZ-WP,E006696,LFCSP16-3X3-PAD1_5X1_5,N/A
U2 = AD9783: User Part Number: UPN; part number: AD9783_SM-AD9783BCPZ,E007614,QFN72_10X10_PAD4_7X4_7,N/A
U3 = ICSY89833: User Part Number: UPN; part number: ICSY89833_SM-SY89833LMG,E007967,MLF16_3X3_PAD1_6X1_6
U4 = ADL5375: User Part Number: UPN; part number: ADL5375_SM-ADL5375-05ACPZ-R7,E007336,QFN24_4X4_PAD2_5X2_5,N/A
VR1 = ADP2114_PRELIM: User Part Number: UPN; part number: ADP2114_PRELIM_SM-ADP2114_PRELIM,E008105,QFN32_5X5_PAD3_3X3_3,N/A
XC3 = CAP: Tolerance: -20/+80; User Part Number: UPN; part number: CAP_SM-.47UF,16V,-20/+80,E000323,C0603; tolerance: -20/+80
XC4 = CAPP: Tolerance: 10; User Part Number: UPN; part number: CAPP_SM-10UF,10V,10,E000690,C3216; tolerance: 10
XC5-XC8 XC11 XC58 = CAP: Tolerance: 10; User Part Number: UPN; part number: CAP_SM-0.1UF,25V,10,E007204,C0603; tolerance: 10
XC12 XC57 = CAP: Tolerance: 10; User Part Number: UPN; part number: CAP_SM-1UF,16V,10,E006882,C0603; tolerance: 10
XCR1 = DIOSCHOTTKY: Tolerance: N/A; User Part Number: UPN; part number: DIOSCHOTTKY_SM-BAT46W-7-F,100V,N/A,E011924,SOD123-3; tolerance: N/A
XD1 = DIOLED: Tolerance: N/A; User Part Number: UPN; part number: DIOLED_SM-CCL-CRS10G (GREEN),2.0V,N/A,E011569,LEDSML118W100H48; tolerance: N/A
XP1 = CN6P: User Part Number: UPN; part number: CN6P_TH-SAMTECTSW10608GS6PIN,E000872,CNBERG1X6H205LD36
XP2 = CN5P_4PSHLD_A: User Part Number: UPN; part number: CN5P_4PSHLD_A_TH-MUSB-05-F-AB-SM-A-R,E006666,CNSAM-MUSB-05-F-AB-SM-A-R
XP3 = CN6P: User Part Number: UPN; part number: CN6P_TH-SAMTECSSW10601GS,E000870,CNBERGF1X6H330LD31
XR2 = RES: Tolerance: 1; User Part Number: UPN; part number: RES_SM-1K,1/10W,1,E003678,R0603; tolerance: 1
XR3 = RES: Tolerance: 1; User Part Number: UPN; part number: RES_SM-1M,1/10W,1,E003682,R0603; tolerance: 1
XR4 = RES: Tolerance: 1; User Part Number: UPN; part number: RES_SM-200,1/4W,1,E003209,R1206; tolerance: 1
XR6 = RES: Tolerance: 5; User Part Number: UPN; part number: RES_SM-0,1/16W,5,E003438,R0402; tolerance: 5
XU1 = ADG3308: User Part Number: UPN; part number: ADG3308_SM-ADG3308BCPZ,E007592,QFN20_4X4_PAD2_1X2_1,N/A
XU2 = ICPIC18F4550: User Part Number: UPN; part number: ICPIC18F4550_SM-PIC18F4550-I/ML,E007514,QFN44_8X8_PAD6_55X6_55
XY1 = XTALACABM8: User Part Number: UPN; part number: XTALACABM8_SM-20.000MHZ,E007421,XTALABM3B

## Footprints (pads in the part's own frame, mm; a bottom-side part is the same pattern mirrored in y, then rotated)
C0306
  rect 0.889x1.524 smd: 1(-0.597,0) 2(0.597,0)
C0402
  rect 0.889x0.813 smd: 1(-0.635,0) 2(0.635,0)
C0603
  rect 1.092x1.194 smd: 1(-0.851,0) 2(0.851,0)
C0603-4P
  rect 0.635x0.889 smd: 1(-0.826,0) 3(0.826,0)
  round 0.127 smd: 2(0,-0.635) 4(0,0.635)
C0805H60
  rect 1.295x1.6 smd: 1(-0.953,0) 2(0.953,0)
C3216
  rect 2.032x1.194 smd: N(1.397,0) P(-1.397,0)
CNBERG1X6H205LD36
  rect 1.651x1.651 hole 1.143: 1(0,0)
  round 1.651 hole 1.143: 2(2.54,0) 3(5.08,0) 4(7.62,0) 5(10.16,0) 6(12.7,0)
CNBERG69157-102
  rect 1.524x1.524 hole 1.016: 1(0,0)
  round 1.524 hole 1.016: 2(2.54,0)
CNBERGF1X6H330LD31
  rect 1.524x1.524 hole 1.016: 1(0,0)
  round 1.524 hole 1.016: 2(2.54,0) 3(5.08,0) 4(7.62,0) 5(10.16,0) 6(12.7,0)
CNDELTRON-571
  rect 2.413x2.413 hole 1.905: 1(0,0)
  round 2.413 hole 1.905: 2(15.3,0)
CNJOHNSON142-0701-201
  round 2.032 hole 1.524: 1(0,0) 2(-2.54,2.54) 3(2.54,2.54) 4(2.54,-2.54) 5(-2.54,-2.54)
CNJOHNSON142-0701-851
  rect 5.08x0.254 smd: 1(0,0)
  rect 5.08x2.413 smd: 2(0,4.381) 3(0,4.381) 4(0,-4.381) 5(0,-4.381)
CNLOOPTP
  round 2.159 hole 1.6: 1(0,0)
CNSAM-MUSB-05-F-AB-SM-A-R
  round 2.261 hole 1.016 unplated: (-2.2,0.15) (2.2,0.15)
  rect 0.508x2.261 smd: 1(-1.6,2.839) 2(-0.8,2.839) 3(0,2.839) 4(0.8,2.839) 5(1.7,2.839)
  rect 2.007x2.489 smd: PAD1(-4.453,2.725) PAD2(4.453,2.725) PAD3(4.453,-2.725) PAD4(-4.453,-2.725)
CNTYCO1469028-1
  rect 1.143x1.143 hole 0.635: A1(0,0)
  round 1.143 hole 0.635: A2(2.5,0) A3(5,0) A4(7.5,0) A5(10,0) A6(12.5,0) A7(15,0) A8(17.5,0) A9(20,0) A10(22.5,0) B1(0,-1.5) B2(2.5,-1.5) B3(5,-1.5) B4(7.5,-1.5) B5(10,-1.5) B6(12.5,-1.5) B7(15,-1.5) B8(17.5,-1.5) B9(20,-1.5) B10(22.5,-1.5) BG1(0,-3) BG2(2.5,-3) BG3(5,-3) BG4(7.5,-3) BG5(10,-3) BG6(12.5,-3) BG7(15,-3) BG8(17.5,-3) BG9(20,-3) BG10(22.5,-3) C1(0,-4.5) C2(2.5,-4.5) C3(5,-4.5) C4(7.5,-4.5) C5(10,-4.5) C6(12.5,-4.5) C7(15,-4.5) C8(17.5,-4.5) C9(20,-4.5) C10(22.5,-4.5) D1(0,-6) D2(2.5,-6) D3(5,-6) D4(7.5,-6) D5(10,-6) D6(12.5,-6) D7(15,-6) D8(17.5,-6) D9(20,-6) D10(22.5,-6) DG1(0,-7.5) DG2(2.5,-7.5) DG3(5,-7.5) DG4(7.5,-7.5) DG5(10,-7.5) DG6(12.5,-7.5) DG7(15,-7.5) DG8(17.5,-7.5) DG9(20,-7.5) DG10(22.5,-7.5)
INDL177W126H71
  rect 1.194x2.794 smd: 1(-2.097,0) 2(2.097,0)
JPRSLD03
  rect 0.61x1.524 smd: 1(-0.838,0) 2(0,0) 3(0.838,0)
L0402
  rect 0.889x0.813 smd: 1(-0.635,0) 2(0.635,0)
L0603
  rect 0.889x0.813 smd: 1(-0.737,0) 2(0.737,0)
LEDSML118W100H48
  rect 2.007x2.489 smd: A(1.499,0) C(-1.499,0)
LFCSP16-3X3-PAD1_5X1_5
  oval 0.279x0.762 smd: 1(-0.75,-1.381) 2(-0.25,-1.381) 3(0.25,-1.381) 4(0.75,-1.381) 9(0.75,1.381) 10(0.25,1.381) 11(-0.25,1.381) 12(-0.75,1.381)
  oval 0.762x0.279 smd: 5(1.381,-0.75) 6(1.381,-0.25) 7(1.381,0.25) 8(1.381,0.75) 13(-1.381,0.75) 14(-1.381,0.25) 15(-1.381,-0.25) 16(-1.381,-0.75)
  rect 1.524x1.524 smd: PAD(0,0)
MINICD542
  rect 1.651x2.54 smd: 1(-2.54,-2.54) 2(0,-2.54) 3(2.54,-2.54) 4(2.54,2.54) 5(0,2.54) 6(-2.54,2.54)
MLF16_3X3_PAD1_6X1_6
  rect 0.229x0.483 smd: 1(-0.75,-1.361) 2(-0.25,-1.361) 3(0.25,-1.361) 4(0.75,-1.361) 9(0.75,1.361) 10(0.25,1.361) 11(-0.25,1.361) 12(-0.75,1.361)
  rect 0.483x0.229 smd: 5(1.361,-0.75) 6(1.361,-0.25) 7(1.361,0.25) 8(1.361,0.75) 13(-1.361,0.75) 14(-1.361,0.25) 15(-1.361,-0.25) 16(-1.361,-0.75)
  rect 1.6x1.6 smd: PAD(0,0)
NL1210
  rect 1.143x1.93 smd: 1(-1.575,0) 2(1.575,0)
QFN20_4X4_PAD2_1X2_1
  oval 0.305x1.041 smd: 1(-1,-1.9) 2(-0.5,-1.9) 3(0,-1.9) 4(0.5,-1.9) 5(1,-1.9) 11(1,1.9) 12(0.5,1.9) 13(0,1.9) 14(-0.5,1.9) 15(-1,1.9)
  oval 1.041x0.305 smd: 6(1.9,-1) 7(1.9,-0.5) 8(1.9,0) 9(1.9,0.5) 10(1.9,1) 16(-1.9,1) 17(-1.9,0.5) 18(-1.9,0) 19(-1.9,-0.5) 20(-1.9,-1)
  rect 2.108x2.108 smd: PAD(0,0)
QFN24_4X4_PAD2_5X2_5
  oval 0.305x0.991 smd: 1(-1.25,-2) 2(-0.75,-2) 3(-0.25,-2) 4(0.25,-2) 5(0.75,-2) 6(1.25,-2) 13(1.25,2) 14(0.75,2) 15(0.25,2) 16(-0.25,2) 17(-0.75,2) 18(-1.25,2)
  oval 0.991x0.305 smd: 7(2,-1.25) 8(2,-0.75) 9(2,-0.25) 10(2,0.25) 11(2,0.75) 12(2,1.25) 19(-2,1.25) 20(-2,0.75) 21(-2,0.25) 22(-2,-0.25) 23(-2,-0.75) 24(-2,-1.25)
  rect 2.489x2.489 smd: PAD(0,0)
QFN32_5X5_PAD3_3X3_3
  oval 0.305x0.889 smd: 1(-1.75,-2.45) 2(-1.25,-2.45) 3(-0.75,-2.45) 4(-0.25,-2.45) 5(0.25,-2.45) 6(0.75,-2.45) 7(1.25,-2.45) 8(1.75,-2.45) 17(1.75,2.45) 18(1.25,2.45) 19(0.75,2.45) 20(0.25,2.45) 21(-0.25,2.45) 22(-0.75,2.45) 23(-1.25,2.45) 24(-1.75,2.45)
  oval 0.889x0.305 smd: 9(2.45,-1.75) 10(2.45,-1.25) 11(2.45,-0.75) 12(2.45,-0.25) 13(2.45,0.25) 14(2.45,0.75) 15(2.45,1.25) 16(2.45,1.75) 25(-2.45,1.75) 26(-2.45,1.25) 27(-2.45,0.75) 28(-2.45,0.25) 29(-2.45,-0.25) 30(-2.45,-0.75) 31(-2.45,-1.25) 32(-2.45,-1.75)
  rect 3.302x3.302 smd: PAD(0,0)
QFN44_8X8_PAD6_55X6_55
  oval 0.381x0.991 smd: 1(-3.25,-4) 2(-2.6,-4) 3(-1.95,-4) 4(-1.3,-4) 5(-0.65,-4) 6(0,-4) 7(0.65,-4) 8(1.3,-4) 9(1.95,-4) 10(2.6,-4) 11(3.25,-4) 23(3.25,4) 24(2.6,4) 25(1.95,4) 26(1.3,4) 27(0.65,4) 28(0,4) 29(-0.65,4) 30(-1.3,4) 31(-1.95,4) 32(-2.6,4) 33(-3.25,4)
  oval 0.991x0.381 smd: 12(4,-3.25) 13(4,-2.6) 14(4,-1.95) 15(4,-1.3) 16(4,-0.65) 17(4,0) 18(4,0.65) 19(4,1.3) 20(4,1.95) 21(4,2.6) 22(4,3.25) 34(-4,3.25) 35(-4,2.6) 36(-4,1.95) 37(-4,1.3) 38(-4,0.65) 39(-4,0) 40(-4,-0.65) 41(-4,-1.3) 42(-4,-1.95) 43(-4,-2.6) 44(-4,-3.25)
  rect 6.553x6.553 smd: PAD(0,0)
QFN72_10X10_PAD4_7X4_7
  oval 0.305x0.94 smd: 1(-4.25,-4.95) 2(-3.75,-4.95) 3(-3.25,-4.95) 4(-2.75,-4.95) 5(-2.25,-4.95) 6(-1.75,-4.95) 7(-1.25,-4.95) 8(-0.75,-4.95) 9(-0.25,-4.95) 10(0.25,-4.95) 11(0.75,-4.95) 12(1.25,-4.95) 13(1.75,-4.95) 14(2.25,-4.95) 15(2.75,-4.95) 16(3.25,-4.95) 17(3.75,-4.95) 18(4.25,-4.95) 37(4.25,4.95) 38(3.75,4.95) 39(3.25,4.95) 40(2.75,4.95) 41(2.25,4.95) 42(1.75,4.95) 43(1.25,4.95) 44(0.75,4.95) 45(0.25,4.95) 46(-0.25,4.95) 47(-0.75,4.95) 48(-1.25,4.95) 49(-1.75,4.95) 50(-2.25,4.95) 51(-2.75,4.95) 52(-3.25,4.95) 53(-3.75,4.95) 54(-4.25,4.95)
  oval 0.94x0.305 smd: 19(4.95,-4.25) 20(4.95,-3.75) 21(4.95,-3.25) 22(4.95,-2.75) 23(4.95,-2.25) 24(4.95,-1.75) 25(4.95,-1.25) 26(4.95,-0.75) 27(4.95,-0.25) 28(4.95,0.25) 29(4.95,0.75) 30(4.95,1.25) 31(4.95,1.75) 32(4.95,2.25) 33(4.95,2.75) 34(4.95,3.25) 35(4.95,3.75) 36(4.95,4.25) 55(-4.95,4.25) 56(-4.95,3.75) 57(-4.95,3.25) 58(-4.95,2.75) 59(-4.95,2.25) 60(-4.95,1.75) 61(-4.95,1.25) 62(-4.95,0.75) 63(-4.95,0.25) 64(-4.95,-0.25) 65(-4.95,-0.75) 66(-4.95,-1.25) 67(-4.95,-1.75) 68(-4.95,-2.25) 69(-4.95,-2.75) 70(-4.95,-3.25) 71(-4.95,-3.75) 72(-4.95,-4.25)
  rect 4.699x4.699 smd: PAD(0,0)
R0402
  rect 0.889x0.813 smd: 1(-0.635,0) 2(0.635,0)
R0603
  rect 1.092x1.194 smd: 1(-0.851,0) 2(0.851,0)
R0805
  rect 1.295x1.397 smd: 1(-0.953,0) 2(0.953,0)
R1206
  rect 1.6x1.6 smd: 1(-1.397,0) 2(1.397,0)
SC-70-3
  rect 0.584x1.118 smd: 1(-0.65,-1.144) 2(0.65,-1.144) 3(0,1.144)
SOD123-3
  rect 1.194x0.711 smd: A(1.847,0) C(-1.847,0)
SWB3S1000
  rect 1.524x1.27 smd: 1(3.937,-2.286) 2(-3.937,-2.286) 3(3.937,2.286) 4(-3.937,2.286)
TSMTYCOSM138-2
  rect 0.914x1.905 smd: 1(-1.524,-2.108) 3(1.524,-2.108) 4(1.524,2.108) 5(0,2.108) 6(-1.524,2.108)
unnamed
  round 5.207 hole 3.937 unplated: (0,0)
XTALABM3B
  rect 1.803x1.194 smd: 1(-2,-1.2) 2(2,-1.2) 3(2,1.2) 4(-2,1.2)

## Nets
AVDD5: C1.1(N1) C5.1(N1) C108.1(N1) C132.1(N1) C200.1(N1) C230.1(N1) E6.2(N2) JP15.2(S2) U4.18(VPS1) U4.24(VPS2)
AVDD33: C46.P(N1) C52.1(N1) C85.1(N1) C86.1(N1) C87.1(N1) C88.1(N1) C89.1(N1) C90.1(N1) C92.P(N1) JP1.2(S2) TP3.1(N1) U2.56(AVDD33_1) U2.57(AVDD33_2) U2.71(AVDD33_3) U2.72(AVDD33_4)
DVDD18: C25.1(N1) C50.P(N1) C55.1(N1) C67.1(N1) C70.1(N1) C73.P(N1) C77.1(N1) C104.1(N1) C106.1(N1) JP8.2(S2) TP9.1(N1) U2.8(DVDD18_1) U2.47(DVDD18_2)
DVDD33: C2.1(N1) C3.1(N1) C4.1(N1) C6.1(N1) C47.P(N1) C53.1(N1) C63.1(N1) C66.1(N1) C71.1(N1) C72.P(N1) JP2.2(S2) S2.1(N2) S2.2(N3) TP5.1(N1) U2.27(DVDD33) U3.7(VCC_1) U3.14(VCC_2) XL3.1(N1)
V5: C34.P(N1) C35.P(N1) E6.1(N1) JP15.1(S1) P5.1(N1) P5.2(N2) R17.1(N1) R20.1(N1) R22.1(N1) VR1.13(EN2) VR1.14(VIN4) VR1.15(VIN5) VR1.16(VIN6) VR1.25(VIN3) VR1.26(VIN2) VR1.27(VIN1) VR1.28(EN1)
V18: C39.P(N1) C43.1(N1) C45.1(N1) E4.1(N1) E5.1(N1) JP13.1(S1) JP14.1(S1) L12.2(N2) VR1.9(FB2)
V33: C42.1(N1) C44.1(N1) E1.1(N1) E2.1(N1) E3.1(N1) JP10.1(S1) JP11.1(S1) JP12.1(S1) L4.2(N2) VR1.32(FB1)
APLANE: C1.2(N2) C2.2(N2) C3.2(N2) C4.2(N2) C5.2(N2) C6.2(N2) C7.2(G1) C7.4(G2) C8.2(G1) C8.4(G2) C9.2(G1) C9.4(G2) C10.2(G1) C10.4(G2) C13.2(N2) C14.2(N2) C15.2(N2) C16.2(N2) C17.2(N2) C23.2(N2) C24.2(N2) C25.2(N2) C26.2(G1) C26.4(G2) C27.2(G1) C27.4(G2) C28.2(N2) C31.2(N2) C32.2(N2) C33.2(N2) C34.N(N2) C35.N(N2) C36.2(N2) C37.2(N2) C38.2(N2) C39.N(N2) C40.1(N1) C41.2(N2) C42.2(N2) C43.2(N2) C44.2(N2) C45.2(N2) C46.N(N2) C47.N(N2) C49.N(N2) C50.N(N2) C51.N(N2) C52.2(N2) C53.2(N2) C54.2(N2) C55.2(N2) C56.2(N2) C63.2(N2) C66.2(N2) C67.2(N2) C68.2(N2) C69.2(N2) C70.2(N2) C71.2(N2) C72.N(N2) C73.N(N2) C77.2(N2) C83.2(N2) C84.2(N2) C85.2(N2) C86.2(N2) C87.2(N2) C88.2(N2) C89.2(N2) C90.2(N2) C91.1(N1) C92.N(N2) C102.N(N2) C103.2(N2) C104.2(N2) C105.2(N2) C106.2(N2) C107.2(N2) C108.2(N2) C132.2(N2) C200.2(N2) C230.2(N2) J1.2(SH1) J1.3(SH2) J1.4(SH3) J1.5(SH4) J2.2(SH1) J2.3(SH2) J2.4(SH3) J2.5(SH4) J5.2(SH1) J5.3(SH2) J5.4(SH3) J5.5(SH4) J6.2(SH1) J6.3(SH2) J6.4(SH3) J6.5(SH4) J7.2(SH1) J7.3(SH2) J7.4(SH3) J7.5(SH4) J8.2(SH1) J8.3(SH2) J8.4(SH3) J8.5(SH4) J9.2(SH1) J9.3(SH2) J9.4(SH3) J9.5(SH4) J17.BG1(N1) J17.BG2(N2) J17.BG3(N3) J17.BG4(N4) J17.BG5(N5) J17.BG6(N6) J17.BG7(N7) J17.BG8(N8) J17.BG9(N9) J17.BG10(N10) J17.DG1(N1) J17.DG2(N2) J17.DG3(N3) J17.DG4(N4) J17.DG5(N5) J17.DG6(N6) J17.DG7(N7) J17.DG8(N8) J17.DG9(N9) J17.DG10(N10) J18.BG1(N1) J18.BG2(N2) J18.BG3(N3) J18.BG4(N4) J18.BG5(N5) J18.BG6(N6) J18.BG7(N7) J18.BG8(N8) J18.BG9(N9) J18.BG10(N10) J18.DG1(N1) J18.DG2(N2) J18.DG3(N3) J18.DG4(N4) J18.DG5(N5) J18.DG6(N6) J18.DG7(N7) J18.DG8(N8) J18.DG9(N9) J18.DG10(N10) L1.1(N1) L2.1(N1) P6.1(N1) P6.2(N2) R2.1(N1) R3.2(N2) R4.1(N1) R5.2(N2) R8.2(N2) R9.1(N1) R11.2(N2) R14.1(N1) R15.1(N1) R16.2(N2) R18.1(N1) R19.1(N1) R21.1(N1) R31.1(N1) R32.1(N1) R33.1(N1) R34.1(N1) R35.1(N1) R36.1(N1) R37.1(N1) R38.2(N2) R39.1(N1) R40.2(N2) R41.1(N1) R43.1(N1) R44.1(N1) T2.3(PRI) TP4.1(N1) TP6.1(N1) TP8.1(N1) TP10.1(N1) TP12.1(N1) TP13.1(N1) U1.7(VEE) U1.14(VEE1) U2.2(CVSS_1) U2.5(CVSS_2) U2.7(DVSS_1) U2.28(DVSS_2) U2.48(DVSS_3) U2.58(AVSS_1) U2.61(AVSS_2) U2.64(AVSS_3) U2.67(AVSS_4) U2.70(AVSS_5) U2.PAD U3.13(GND) U3.PAD U4.2(COMM1) U4.5(COMM2) U4.12(COMM5) U4.14(COMM6) U4.17(COMM7) U4.19(COMM8) U4.PAD VR1.1(GND) VR1.4(SCFG) VR1.6(OPCFG) VR1.19(PGND4) VR1.20(PGND3) VR1.21(PGND2) VR1.22(PGND1) VR1.PAD XC1.1(N1) XC2.1(N1) XC3.1(N1) XC4.N(N2) XC5.1(N1) XC6.1(N1) XC7.1(N1) XC8.1(N1) XC11.1(N1) XC12.2(N2) XC57.2(N2) XC58.1(N1) XD1.C(N) XP1.6(N6) XP2.5(N5) XP2.PAD1(GND1) XP2.PAD2(GND2) XP2.PAD3(GND3) XP2.PAD4(GND4) XP3.6(N6) XU1.9(GND) XU1.PAD XU2.6(VSS1) XU2.30(VSS2) XU2.31(VSS3) XU2.PAD XY1.2(GND) XY1.4(GND1)
CLKN: C21.2(N2) R13.1(N1) U2.4(CLKN)
CLKP: C20.2(N2) R12.2(N2) U2.3(CLKP)
CSB: U2.52(CSB) XJP4.1(S1) XP3.5(N5)
CVDD18: C28.1(N1) C51.P(N1) C56.1(N1) C68.1(N1) C69.1(N1) C83.1(N1) C102.P(N1) C103.1(N1) C105.1(N1) JP9.2(S2) R10.1(N1) TP11.1(N1) U2.1(CVDD18_1) U2.6(CVDD18_2)
CVDD33: C15.1(N1) C16.1(N1) C49.P(N1) C54.1(N1) C84.1(N1) C107.1(N1) JP3.2(S2) TP7.1(N1) U1.8(VCC) U1.13(VCC1)
D: C18.2(N2) U1.1(D)
D0N: J18.B8(N8) U2.46(D0N)
D0P: J18.A8(N8) U2.45(D0P)
D1N: J18.B7(N7) U2.44(D1N)
D1P: J18.A7(N7) U2.43(D1P)
D2N: J18.B6(N6) U2.42(D2N)
D2P: J18.A6(N6) U2.41(D2P)
D3N: J18.B5(N5) U2.40(D3N)
D3P: J18.A5(N5) U2.39(D3P)
D4N: J18.B4(N4) U2.38(D4N)
D4P: J18.A4(N4) U2.37(D4P)
D5N: J18.B3(N3) U2.36(D5N)
D5P: J18.A3(N3) U2.35(D5P)
D6N: J18.B2(N2) U2.34(D6N)
D6P: J18.A2(N2) U2.33(D6P)
D7N: J18.B1(N1) U2.32(D7N)
D7P: J18.A1(N1) U2.31(D7P)
D8N: J17.B10(N10) U2.24(D8N)
D8P: J17.A10(N10) U2.23(D8P)
D9N: J17.B9(N9) U2.22(D9N)
D9P: J17.A9(N9) U2.21(D9P)
D10N: J17.B8(N8) U2.20(D10N)
D10P: J17.A8(N8) U2.19(D10P)
D11N: J17.B7(N7) U2.18(D11N)
D11P: J17.A7(N7) U2.17(D11P)
D12N: J17.B6(N6) U2.16(D12N)
D12P: J17.A6(N6) U2.15(D12P)
D13N: J17.B5(N5) U2.14(D13N)
D13P: J17.A5(N5) U2.13(D13P)
D14N: J17.B4(N4) U2.12(D14N)
D14P: J17.A4(N4) U2.11(D14P)
D15N: J17.B3(N3) U2.10(D15N)
D15P: J17.A3(N3) U2.9(D15P)
D-: C19.2(N2) U1.2(D_N)
DCI_N: J17.B2(N2) U2.30(DCIN)
DCI_P: J17.A2(N2) U2.29(DCIP)
DCO_N: U2.26(DCON) U3.9(IN_N)
DCO_P: U2.25(DCOP) U3.12(IN)
DSOP: U4.1(DSOP)
INTERNAL_MISO: XR6.2(N2) XU1.15(Y3) XU2.9(RB0_AN12_INT0_FLT0_SDI_SDA)
INTERNAL_MOSI: XR6.1(N1) XU1.16(Y2) XU2.1(RC7_RX_DT_SDO)
INTERNAL_SCK: XU1.17(Y1) XU2.10(RB1_AN10_INT1_SCK_SCL)
INTERNAL_SLAVE_SS: XU1.10(Y8) XU2.24(RA5_AN4_SS_HLVDIN_C2OUT)
IOUT1N: JP5.1(A) L11.1(N1)
IOUT1P: JP4.1(A) L10.1(N1)
IOUT2N: JP7.1(A) L9.1(N1)
IOUT2P: JP6.1(A) L8.1(N1)
IRQ: TP14.1(N1) XU1.5(A6)
PGOOD18: R20.2(N2) VR1.12(PGOOD2)
PGOOD33: R22.2(N2) VR1.29(PGOOD1)
Q1_N: J17.B1(N1) U3.2(Q1_N)
Q1_P: J17.A1(N1) U3.1(Q1)
Q2_N: J18.D10(N10) U3.4(Q2_N)
Q2_P: J18.C10(N10) U3.3(Q2)
SCLK: U2.51(SCLK) XJP5.1(S1) XP3.2(N2)
SDIO: U2.50(SDIO) XJP1.1(S1) XP3.3(N3)
SDO: U2.49(SDO) XJP3.1(S1) XP3.4(N4)
SYNC: TP2.1(N1) VR1.5(SYNC_CLKOUT)
UNNAMED_3_ICSY89833_I43_Q0: R1.1(N1) U3.15(Q0)
UNNAMED_3_ICSY89833_I43_Q0N: R1.2(N2) U3.16(Q0_N)
UNNAMED_3_ICSY89833_I43_Q3: R30.2(N2) U3.5(Q3)
UNNAMED_3_ICSY89833_I43_Q3N: R30.1(N1) U3.6(Q3_N)
UNNAMED_4_ADL5375_I114_COMM3: L1.2(N2) U4.8(COMM3) U4.11(COMM4)
UNNAMED_4_ADL5375_I114_COMM10: L2.2(N2) U4.20(COMM9) U4.23(COMM10)
UNNAMED_4_ADL5375_I114_IBBN: C26.3(B) C95.1(N1) L6.2(N2) R3.1(N1) R24.1(N1) U4.22(IBBN)
UNNAMED_4_ADL5375_I114_IBBP: C26.1(A) C95.2(N2) L5.2(N2) R2.2(N2) R24.2(N2) U4.21(IBBP)
UNNAMED_4_ADL5375_I114_LOIN: C40.2(N2) U4.4(LOIN)
UNNAMED_4_ADL5375_I114_LOIP: C22.2(N2) U4.3(LOIP)
UNNAMED_4_ADL5375_I114_QBBN: C27.3(B) C100.1(N1) L13.2(N2) R5.1(N1) R23.1(N1) U4.9(QBBN)
UNNAMED_4_ADL5375_I114_QBBP: C27.1(A) C100.2(N2) L7.2(N2) R4.2(N2) R23.2(N2) U4.10(QBBP)
UNNAMED_4_ADL5375_I114_RFOUT: C94.1(N1) U4.16(RFOUT)
UNNAMED_4_CAP_I61_N1: C7.3(B) C48.1(N1) L6.1(N1) L11.2(N2)
UNNAMED_4_CAP_I61_N2: C7.1(A) C48.2(N2) L5.1(N1) L10.2(N2)
UNNAMED_4_CAP_I81_N1: C10.3(B) C98.1(N1) L9.2(N2) L13.1(N1)
UNNAMED_4_CAP_I81_N2: C10.1(A) C98.2(N2) L7.1(N1) L8.2(N2)
UNNAMED_4_CAP_I109_N2: C94.2(N2) J6.1(CNTR)
UNNAMED_4_CAP_I111_N1: C22.1(N1) J2.1(CNTR)
UNNAMED_6_ADG3308_I82_A1: XJP5.2(S2) XU1.20(A1)
UNNAMED_6_ADG3308_I82_A2: XJP1.2(S2) XU1.1(A2)
UNNAMED_6_ADG3308_I82_A3: XJP3.2(S2) XU1.2(A3)
UNNAMED_6_ADG3308_I82_A4: XJP4.2(S2) XU1.3(A4)
UNNAMED_6_ADG3308_I82_EN: XR1.1(N1) XU1.8(EN)
UNNAMED_6_ADG3308_I82_VCCA: XC11.2(N2) XC12.1(N1) XCR1.A(P) XL3.2(N2) XP3.1(N1) XR1.2(N2) XU1.19(VCCA)
UNNAMED_6_ADG3308_I82_Y4: XU1.14(Y4) XU2.38(RD0_SPP0)
UNNAMED_6_ADG3308_I82_Y6: XU1.12(Y6) XU2.40(RD2_SPP2)
UNNAMED_6_ADG3308_I82_Y7: XU1.11(Y7) XU2.41(RD3_SPP3)
UNNAMED_6_CAP_I4_N2: XC1.2(N2) XR3.1(N1) XU2.32(OSC1_CLKI) XY1.1(N1)
UNNAMED_6_CAP_I5_N2: XC2.2(N2) XR3.2(N2) XU2.33(OSC2_CLKO_RA6) XY1.3(N2)
UNNAMED_6_CAP_I11_N2: XC3.2(N2) XU2.37(VUSB)
UNNAMED_6_CN6P_I38_N1: XP1.1(N1) XU2.17(RB7_KBI3_PGD)
UNNAMED_6_CN6P_I38_N3: XP1.3(N3) XU2.16(RB6_KBI2_PGC)
UNNAMED_6_CN6P_I38_N4: XP1.4(N4) XU2.15(RB5_KBI1_PGM)
UNNAMED_6_CN6P_I38_N5: XP1.5(N5) XR2.2(N2) XU2.18(MCLR_VPP_RE3)
UNNAMED_6_DIOLED_I107_P: XD1.A(P) XR4.2(N2)
UNNAMED_6_ICPIC18F4550_I2_RC2CC: XR4.1(N1) XU2.36(RC2_CCP1_P1A)
UNNAMED_11_AD9783_I190_FSADJ: R21.2(N2) U2.54(FS_ADJ)
UNNAMED_11_AD9783_I190_RESET: C17.1(N1) R7.2(N2) R31.2(N2) U2.53(RESET)
UNNAMED_11_ADCLK905_I248_PAD: C14.1(N1) U1.PAD
UNNAMED_11_ADCLK905_I248_Q: C20.1(N1) R8.1(N1) U1.12(Q)
UNNAMED_11_ADCLK905_I248_QN: C21.1(N1) R9.2(N2) U1.11(Q_N)
UNNAMED_11_ADCLK905_I248_VREF: C13.1(N1) U1.15(VREF) U1.16(VT)
UNNAMED_11_CAP_I216_N2: C91.2(N2) TP16.1(N1) U2.55(REFIO)
UNNAMED_11_CAP_I281_N1: C18.1(N1) CR4.3(C) R6.1(N1) T2.6(SEC_DOT)
UNNAMED_11_CAP_I283_N1: C19.1(N1) CR4.1(P) CR4.2(N) R6.2(N2) T2.4(SEC)
UNNAMED_11_CNBNC5P_I5_CNTR: J5.1(CNTR) JP21.2(S2) R38.1(N1) T7.3(PRIP)
UNNAMED_11_CNBNC5P_I6_CNTR: J7.1(CNTR) JP22.2(S2) R39.2(N2) T7.1(PRIN)
UNNAMED_11_CNBNC5P_I8_CNTR: J8.1(CNTR) JP23.2(S2) R40.1(N1) T8.3(PRIP)
UNNAMED_11_CNBNC5P_I14_CNTR: J9.1(CNTR) JP24.2(S2) R41.2(N2) T8.1(PRIN)
UNNAMED_11_CNBNC5P_I288_CNTR: J1.1(CNTR) T2.1(PRI_DOT)
UNNAMED_11_NC2PJMPROPEN_I17_S1: JP4.3(B) JP21.1(S1) T7.4(SECP)
UNNAMED_11_NC2PJMPROPEN_I40_S1: JP5.3(B) JP22.1(S1) T7.6(SECN)
UNNAMED_11_NC2PJMPROPEN_I42_S1: JP7.3(B) JP23.1(S1) T8.4(SECP)
UNNAMED_11_NC2PJMPROPEN_I49_S1: JP6.3(B) JP24.1(S1) T8.6(SECN)
UNNAMED_11_NC3PJMPR_I22_COM: C8.3(B) C30.1(N1) JP4.2(COM) R28.2(N2) R34.2(N2) U2.69(IOUT1P)
UNNAMED_11_NC3PJMPR_I53_COM: C8.1(A) C30.2(N2) JP5.2(COM) R26.2(N2) R36.2(N2) U2.68(IOUT1N)
UNNAMED_11_NC3PJMPR_I55_COM: C9.1(A) C29.1(N1) JP6.2(COM) R29.2(N2) R35.2(N2) U2.59(IOUT2P)
UNNAMED_11_NC3PJMPR_I56_COM: C9.3(B) C29.2(N2) JP7.2(COM) R27.2(N2) R37.2(N2) U2.60(IOUT2N)
UNNAMED_11_RES_I65_N1: R28.1(N1) R43.2(N2) U2.66(AUX1P)
UNNAMED_11_RES_I66_N1: R26.1(N1) R32.2(N2) U2.65(AUX1N)
UNNAMED_11_RES_I70_N1: R29.1(N1) R44.2(N2) U2.62(AUX2P)
UNNAMED_11_RES_I71_N1: R27.1(N1) R33.2(N2) U2.63(AUX2N)
UNNAMED_11_RES_I272_N2: R14.2(N2) T7.5(SECCT)
UNNAMED_11_RES_I273_N2: R15.2(N2) T8.5(SECCT)
UNNAMED_11_RES_I277_N1: R7.1(N1) S2.3(N5) S2.4(N4)
UNNAMED_12_ADP2114PRELIM_I1_C_1: R25.1(N1) VR1.7(COMP2)
UNNAMED_12_ADP2114PRELIM_I1_COM: R42.1(N1) VR1.2(COMP1)
UNNAMED_12_ADP2114PRELIM_I1_FRE: R16.1(N1) TP1.1(N1) VR1.3(FREQ)
UNNAMED_12_ADP2114PRELIM_I1_SS1: C32.1(N1) VR1.30(SS1)
UNNAMED_12_ADP2114PRELIM_I1_SS2: C33.1(N1) VR1.11(SS2)
UNNAMED_12_ADP2114PRELIM_I1_SW1: L4.1(N1) VR1.23(SW2) VR1.24(SW1)
UNNAMED_12_ADP2114PRELIM_I1_SW3: L12.1(N1) VR1.17(SW4) VR1.18(SW3)
UNNAMED_12_ADP2114PRELIM_I1_V1S: R18.2(N2) VR1.31(V1SET)
UNNAMED_12_ADP2114PRELIM_I1_V2S: R19.2(N2) VR1.10(V2SET)
UNNAMED_12_ADP2114PRELIM_I1_VDD: C31.1(N1) R17.2(N2) VR1.8(VDD)
UNNAMED_12_CAP_I32_N1: C38.1(N1) C41.1(N1) R42.2(N2)
UNNAMED_12_CAP_I46_N1: C36.1(N1) C37.1(N1) R25.2(N2)
UNNAMED_12_CNJMPRSHRT_I19_S1: E1.2(N2) JP1.1(S1) JP10.2(S2)
UNNAMED_12_CNJMPRSHRT_I75_S1: E2.2(N2) JP2.1(S1) JP11.2(S2)
UNNAMED_12_CNJMPRSHRT_I84_S1: E3.2(N2) JP3.1(S1) JP12.2(S2)
UNNAMED_12_CNJMPRSHRT_I97_S1: E4.2(N2) JP8.1(S1) JP13.2(S2)
UNNAMED_12_CNJMPRSHRT_I99_S1: E5.2(N2) JP9.1(S1) JP14.2(S2)
USB_D+: XP2.3(N3) XU2.43(RC5_D_POS_VP)
USB_D-: XP2.2(N2) XU2.42(RC4_D_NEG_VM)
USB_VCC: XC4.P(N1) XC5.2(N2) XC6.2(N2) XC7.2(N2) XC8.2(N2) XC57.1(N1) XC58.2(N2) XCR1.C(N) XP1.2(N2) XP2.1(N1) XR2.1(N1) XU1.18(VCCY) XU2.7(VDD1) XU2.8(VDD2) XU2.28(VDD3) XU2.29(VDD4)
VCB: C23.1(N1) C24.1(N1) R10.2(N2) R11.1(N1) R12.1(N1) R13.2(N2)

Pads without a net: J17 C1 C2 C3 C4 C5 C6 C7 C8 C9 C10 D1 D2 D3 D4 D5 D6 D7 D8 D9 D10; J18 A9 A10 B9 B10 C1 C2 C3 C4 C5 C6 C7 C8 C9 D1 D2 D3 D4 D5 D6 D7 D8 D9; T2 5; T7 2; T8 2; U1 3 4 5 6 9 10; U3 8 10 11; U4 6 7 13 15; XP2 4; XU1 4 6 7 13; XU2 2 3 4 5 11 12 13 14 19 20 21 22 23 25 26 27 34 35 39 44

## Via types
v1: diameter 0.762, hole 0.406, TOP to BOTTOM, 449 vias
v2: diameter 0.508, hole 0.254, TOP to BOTTOM, 100 vias

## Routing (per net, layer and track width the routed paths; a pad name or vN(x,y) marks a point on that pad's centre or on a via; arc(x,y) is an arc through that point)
AVDD5: length 16.6
  TOP w0.254: U4.18 98.27,55.34 v1(98.55,55.63)
  TOP w0.279: U4.24 94.86,55.75 93.98,55.75
  TOP w0.508: v1(98.55,55.63) 98.93,56.01 C1.1 ; C200.1 v1(94.87,58.8) ; JP15.2 v1(108.33,92.96) ; v1(111.63,90.04) E6.2 v1(109.16,91.25) ; 93.98,55.75 v1(93.34,56.39) C5.1 C132.1 v1(90.55,56.39) ; v1(99.69,58.17) 99.82,58.29 C230.1 ; C108.1 v1(99.69,56.64)
  TOP w0.635: C1.1 v1(99.69,56.64) ; C108.1 v1(99.69,58.17) ; C230.1 v1(99.82,60.07)
AVDD33: length 30.7
  TOP w0.203: 58.17,49.91 58.17,50.16 57.91,50.42 U2.57
  TOP w0.279: U2.72 57.39,57.92 57.51,57.79 v2(57.78,57.79) ; v1(58.29,49.78) 58.16,49.92 U2.56 ; v2(57.78,57.79) 57.78,58.31 58.41,58.93 58.67,58.93 C89.1 ; v2(57.78,57.79) 57.41,57.42 U2.71
  TOP w0.508: C90.1 v1(58.29,49.78) ; v1(99.19,83.44) C92.P v1(97.41,82.04) ; TP3.1 104.14,85.98 C46.P C52.1
  L4PWR w0.508: 100.33,84.53 JP1.2 ; JP1.2 101.52,85.72 ; JP1.2 99.14,85.72 ; JP1.2 100.33,86.92 ; TP3.1 104.39,87.24 ; TP3.1 105.91,85.72 ; TP3.1 104.39,84.21 ; TP3.1 102.88,85.72
  BOTTOM w0.508: C85.1 57.28,57.28 57.65,57.65 57.65,57.66 v2(57.78,57.79) 57.78,58.55 58.17,58.93 C87.1 ; C90.1 v1(58.29,49.78) C86.1
DVDD18: length 25.3
  TOP w0.279: U2.8 v1(53.02,60.26) ; U2.47 53.02,47.81 v1(53.09,47.75) 53.09,47.12 C106.1
  TOP w0.508: C73.P v1(20.83,82.55) ; TP9.1 22.61,92.46 C50.P C55.1 ; C70.1 v1(53.02,60.26)
  L3PWR w0.508: 21.35,92.2 TP9.1 ; TP9.1 22.86,90.69 ; TP9.1 24.37,92.2 ; TP9.1 22.86,93.71 ; 17.6,92.2 JP8.2 ; JP8.2 18.8,93.4 ; JP8.2 18.8,91.01 ; JP8.2 19.99,92.2
  BOTTOM w0.279: C106.1 53.09,47.12 v1(53.09,47.75)
  BOTTOM w0.508: C25.1 v1(52.45,63.25) ; C70.1 v1(53.02,60.26) ; C77.1 v1(53.34,44.07)
DVDD33: length 32.8
  TOP w0.279: U2.27 v1(46.43,53.92)
  TOP w0.381: S2.1 v1(74.22,19.3) ; S2.2 v1(63.93,19.3)
  TOP w0.508: C72.P v1(3.43,85.34) ; TP5.1 9.02,92.46 C47.P C53.1
  L3PWR w0.508: TP5.1 10.78,92.2 ; TP5.1 9.27,90.69 ; TP5.1 9.27,93.71 ; TP5.1 7.76,92.2 ; 4.01,92.2 JP2.2 ; JP2.2 5.21,93.4 ; JP2.2 5.21,91.01 ; JP2.2 6.4,92.2
  BOTTOM w0.279: v1(19.56,44.2) 19.43,44.33 U3.14 ; v1(20.07,48.89) 19.81,48.89 19.43,48.51 U3.7
  BOTTOM w0.508: C71.1 46.23,53.72 v1(46.43,53.92) ; C2.1 v1(22.39,50.63) ; C4.1 v1(22.39,44.92) ; v1(45.09,53.72) 44.45,53.09 C66.1 C63.1 ; C3.1 v1(22.39,48.48) ; XL3.1 v1(49.15,30.23) ; C6.1 v1(22.39,42.67)
V5: length 38.5
  TOP w0.203: 54.1,100.58 54.36,100.84 VR1.28 ; VR1.26 53.36,100.73 53.21,100.58 ; 52.96,110.87 53.15,110.87 ; 53.98,100.58 53.86,100.7 VR1.27 ; 52.35,106.46 VR1.16 52.86,107.26 ; VR1.14 53.86,107.26 ; VR1.25 52.86,100.68 53.09,100.46 ; VR1.13 54.36,107.26 ; 52.2,109.5 C34.P 51.24,110.87 ; 51.12,97.54 C35.P 52.07,98.91 ; VR1.15 53.36,107.26
  TOP w0.508: R17.1 v1(61.34,107.19) ; R20.1 53.47,112.65 53.47,112.14 ; C34.P 52.96,110.87 53.47,111.38 53.47,111.89 ; C35.P 52.96,97.54 53.28,97.22 53.28,96.33 54.23,95.38 ; 108.33,95.38 v1(108.33,96.39) ; v1(109.47,95.44) E6.1 v1(111.63,96.52)
  L3PWR w0.203: P5.1 111.34,114 ; P5.1 109.7,115.63 ; P5.1 109.7,112.36 ; P5.1 108.06,114 ; P5.2 96.04,114 ; P5.2 94.4,112.36 ; P5.2 94.4,115.63 ; P5.2 92.76,114
  vias: v2(51.31,99.44) v2(51.44,100.2) v2(51.82,108.97) v2(52.32,107.31) v2(52.45,108.08) v2(52.45,99.95) v2(53.09,108.84) v2(53.21,108.08) v2(53.47,99.82)
V18: length 30.3
  TOP w0.279: v1(57.91,114.43) 57.91,107.44 56.93,106.46 VR1.9
  TOP w0.508: C39.P 44.83,113.98 C43.1 ; C39.P 44.91,111.3 44.91,108.89 v1(45.34,108.46) 44.91,108.03 L12.2 v1(43.69,107.44) ; C39.P v1(43.43,111.38) ; 44.83,116.2 v1(43.81,116.2) ; 44.83,116.2 44.83,114.11 C43.1 ; 44.83,116.2 v1(44.83,117.09) ; v1(18.8,102.87) E4.1 v1(20.38,101.79) ; v1(32.89,102.62) E5.1 v1(34.35,101.67) ; JP14.1 v1(29.84,101.09) ; C43.1 v1(43.56,114.05) ; JP13.1 v1(15.75,101.09)
V33: length 19.1
  TOP w0.279: VR1.32 56.36,101.12 v1(56.64,100.84)
  TOP w0.508: JP11.1 v1(2.16,101.47) ; JP10.1 v1(97.28,94.87) ; v1(83.69,96.27) E3.1 v1(85.92,95.44) ; v1(102.3,95.32) E1.1 v1(100.33,96.39) ; v1(40.77,100.33) C44.1 v1(41.91,101.22) ; v1(5.21,102.74) E2.1 v1(7.43,101.79) ; v1(47.45,98.88) L4.2 v1(48.39,99.69) ; v1(41.85,104.2) C42.1 v1(40.89,103) ; JP12.1 v1(80.64,95.25)
APLANE: length 761.6
  TOP w0.203: 98.27,54.36 U4.17 ; C10.2 v1(77.22,49.66) ; U2.48 v2(53.52,49.78) ; U2.28 v1(48.26,53.42) ; C27.2 v1(85.98,49.66) ; 98.27,52.83 U4.14 ; C7.2 v1(75.44,58.04) ; 53.52,57.92 U2.7 ; v2(39.47,15.29) 39.55,15.37 XU2.PAD ; C26.4 v1(86.11,57.91) ; v1(61.72,56.13) C8.2 C8.4 v1(59.94,56.13) ; C7.4 v1(77.34,58.04) ; C26.2 v1(83.57,57.91) ; v1(61.72,51.69) C9.2 C9.4 v1(59.94,51.69) ; C10.4 v1(75.18,49.66) ; C27.4 v1(83.69,49.66)
  TOP w0.279: U2.64 v2(56.26,53.92) ; v1(98.29,56.53) 98.28,56.52 98.04,56.52 97.52,55.99 U4.19 ; U4.5 93.36,52.84 v1(92.96,52.45) ; XU1.PAD 39.56,26.86 XU1.9 ; U2.58 v2(56.26,50.92) ; U2.5 v2(54.52,57.53) ; C16.2 52.19,75.7 U1.7 ; U1.14 57.66,75.7 C107.2 ; v1(99.82,51.94) 99.82,52.07 99.06,52.83 98.27,52.83 ; v1(98.42,50.93) 98.3,50.93 97.63,51.59 U4.12 ; VR1.22 51.11,103.26 51.04,103.33 50.72,103.33 50.55,103.5 ; v2(55.63,57.66) 56.02,58.06 U2.2 56.02,60.09 56.52,60.58 C69.2 C68.2 ; v2(53.52,57.53) 53.52,57.92 ; v2(55.63,56.92) U2.70 57.94,56.92 58.8,57.78 v1(59.44,57.78) ; XU2.6 v1(35.13,15.37) ; VR1.21 50.55,103.76 50.55,103.76 ; VR1.20 50.8,104.26 50.67,104.39 ; VR1.19 50.79,104.76 50.55,104.52 ; U4.2 93.23,54.34 v1(92.96,54.61) ; U2.61 v2(56.26,52.42) ; v1(99.95,54.86) 99.44,54.86 98.93,54.36 98.27,54.36 ; U2.67 v2(55.84,55.42)
  TOP w0.305: v1(57.4,101.6) 57.06,101.94 VR1.1 ; VR1.4 54.86,103.76 v2(54.61,104.01) 55.36,104.76 VR1.6
  TOP w0.381: XU2.31 44.91,17.32 v1(45.21,17.02) 44.86,16.67 XU2.30
  TOP w0.508: C54.2 v1(89.53,91.69) ; C16.2 v1(50.67,76.45) C15.2 v1(48.89,76.45) ; C47.N v1(12.83,95.76) ; v1(47.5,34.04) 47.22,33.76 XD1.C ; C52.2 v1(106.17,91.57) ; v1(99.95,54.86) 100.97,55.88 C1.2 C108.2 101.09,57.66 C230.2 ; v1(103.38,82.04) 101.98,82.04 v1(101.98,83.06) ; v1(66.17,46.1) R35.1 ; C41.2 v1(64.64,100.84) ; C43.2 v1(47.75,114.05) ; C49.N v1(91.31,89.41) ; C40.1 v1(90.93,50.67) ; C55.2 v1(24.64,98.04) ; v1(9.02,85.34) C72.N v1(7.49,86.49) ; XC2.1 v1(56.24,23.98) ; C56.2 v1(38.73,97.92) ; R34.1 v1(66.17,61.59) ; R2.1 v1(83.38,60.9) ; C32.2 v1(56.01,97.41) ; C50.N v1(26.42,95.76) ; XP2.PAD3 v1(31.55,2.99) ; R14.1 v1(76.24,60.92) ; XC5.1 v1(45.63,13.93) ; C13.2 v1(60.71,78.49) ; v1(52.07,93.6) C35.N v1(53.21,94.74) ; C46.N v1(107.95,89.28) ; R16.2 v1(61.72,98.68) ; C42.2 v1(44.7,103) ; R37.1 v1(66.17,53.34) ; v1(61.09,76.45) C84.2 v1(59.18,76.45) C107.2 ; v1(26.04,82.55) C73.N v1(24.89,83.57) ; C102.N v1(40.13,83.82) ; 56.77,111.12 v1(56.77,112.01) ; XP2.PAD4 v1(19.11,2.99) ; J2.4 v1(108.14,80.84) ; XC8.1 v1(44.4,29.41) ; v1(52.2,114.81) C34.N v1(51.18,113.66) ; R3.2 v1(83.38,54.8) ; 53.34,45.59 v1(53.34,45.09) ; v1(59.44,48.51) C90.2 ; R5.2 v1(83.5,52.64) ; v1(54.1,62.1) C83.2 ; v1(90.68,55.12) C132.2 C5.2 92.58,54.99 v1(92.96,54.61) ; C17.2 v1(61.72,24.38) ; XC1.1 v1(52.81,13.87) ; XC6.1 v1(30.81,15.82) ; R4.1 v1(83.63,46.93) ; C70.2 v1(51.82,62.1) ; R8.2 v1(58.8,72.14) ; R9.1 v1(51.56,72.14) ; C38.2 v1(62.86,100.84) ; R38.2 v1(75.13,76.25) ; C53.2 v1(11.05,98.04) ; XP2.5 v1(27.1,10.24) ; XY1.4 v1(52.62,16.97) ; XP2.PAD1 v1(19.11,8.44) ; C39.N v1(48.64,111.38) ; C31.2 v1(60.45,109.6) ; C36.2 v1(64.52,107.44) ; R39.1 v1(80.54,76.2) ; R31.1 v1(59.69,23.88) ; v1(108.27,72.07) J2.2 ; R18.1 v1(57.15,96.77) ; v1(66.17,54.23) R36.1 ; T2.3 v1(63.32,88.34) ; v1(56.52,63.25) C68.2 ; XP2.PAD2 v1(31.55,8.44) ; XC3.1 v1(43.83,22.62) ; R15.1 v1(76.24,46.7) ; XY1.2 v1(57,20.97) ; R40.2 v1(80.52,31.88) ; C37.2 v1(62.86,107.31) ; XC4.N v1(49.56,11.96) ; 39.5,95.63 v1(40.51,95.63) ; C33.2 v1(55.75,111.12) ; R41.1 v1(75.13,31.8) ; C45.2 v1(47.37,116.2) ; XC7.1 v1(30.51,13.49) ; C200.2 v1(94.23,60.71) ; C44.2 v1(44.2,100.33)
  TOP w0.61: J6.4 v1(108.84,49.47) ; J6.2 v1(108.71,58.23)
  TOP w0.635: C1.2 v1(101.85,56.01) ; C108.2 v1(101.98,57.53) ; C230.2 v1(101.98,59.31)
  L2GND w0.508: J8.2 85.85,37.31 ; J8.2 84.4,38.76 ; J8.2 84.4,35.86 ; J8.2 82.96,37.31 ; 5.01,41.25 J17.BG9 5.01,43.25 ; 72.85,93.09 J1.3 ; J1.3 74.3,94.54 ; J1.3 74.3,91.64 ; J1.3 75.74,93.09 ; 82.96,32.23 J8.5 ; J8.5 84.4,33.68 ; J8.5 85.85,32.23 ; J8.5 84.4,30.78 ; 9.51,43.75 J17.DG10 ; J17.DG10 9.51,45.75 ; J17.DG10 10.51,44.75 ; 9.51,26.25 J17.DG3 ; J17.DG3 10.51,27.25 ; J17.DG3 9.51,28.25 ; 5.01,47.28 J18.BG1 5.01,49.29 ; 5.01,67.28 J18.BG9 5.01,69.29 ; TP13.1 37.72,109.97 ; TP13.1 39.23,108.46 ; TP13.1 36.21,108.46 ; TP13.1 37.72,106.95 ; TP6.1 13.84,93.71 ; TP6.1 15.35,92.2 ; TP6.1 12.33,92.2 ; TP6.1 13.84,90.69 ; J7.3 91.36,76.23 ; J7.3 89.92,77.67 ; J7.3 89.92,74.78 ; J7.3 88.47,76.23 ; 5.01,59.29 J18.BG5 5.01,57.28 ; 9.51,47.28 J18.DG1 ; J18.DG1 9.51,49.29 ; J18.DG1 10.51,48.29 ; J8.3 89.48,38.76 ; J8.3 90.93,37.31 ; J8.3 88.04,37.31 ; J8.3 89.48,35.86 ; J5.5 67.67,71.2 ; J5.5 64.77,71.2 ; J5.5 66.22,72.64 ; J5.5 66.22,69.75 ; TP12.1 41.53,93.59 ; TP12.1 41.53,90.56 ; TP12.1 40.02,92.08 ; TP12.1 43.04,92.08 ; J8.4 89.48,33.68 ; J8.4 88.04,32.23 ; J8.4 89.48,30.78 ; J8.4 90.93,32.23 ; 9.51,38.75 J17.DG8 ; J17.DG8 10.51,39.75 ; J17.DG8 9.51,40.75 ; J7.5 84.84,72.59 ; J7.5 83.39,71.15 ; J7.5 84.84,69.7 ; J7.5 86.28,71.15 ; 5.01,38.75 J17.BG8 5.01,40.75 ; 66.22,74.83 J5.2 ; J5.2 64.77,76.28 ; J5.2 67.67,76.28 ; J5.2 66.22,77.72 ; J17.DG1 9.51,23.25 ; J17.DG1 9.51,21.25 ; J17.DG1 10.51,22.25 ; 69.37,37.31 J9.3 ; J9.3 70.82,38.76 ; J9.3 70.82,35.86 ; J9.3 72.26,37.31 ; 9.51,59.78 J18.DG6 ; J18.DG6 10.51,60.79 ; J18.DG6 9.51,61.79 ; J18.DG10 10.51,70.79 ; J18.DG10 9.51,71.79 ; J18.DG10 9.51,69.78 ; J18.DG2 9.51,51.79 ; J18.DG2 9.51,49.78 ; J18.DG2 10.51,50.79 ; 34.32,4.23 XP1.6 ; XP1.6 34.32,6.74 ; XP1.6 33.06,5.49 ; XP1.6 35.57,5.49 ; TP8.1 92.33,87.36 ; TP8.1 90.82,85.85 ; TP8.1 92.33,84.34 ; TP8.1 93.84,85.85 ; 72.85,88.01 J1.4 ; J1.4 75.74,88.01 ; J1.4 74.3,89.46 ; J1.4 74.3,86.56 ; J5.4 71.3,72.64 ; J5.4 71.3,69.75 ; J5.4 72.75,71.2 ; J5.4 69.85,71.2 ; 69.85,76.28 J5.3 ; J5.3 72.75,76.28 ; J5.3 71.3,77.72 ; J5.3 71.3,74.83 ; J17.DG9 9.51,43.25 ; J17.DG9 9.51,41.25 ; J17.DG9 10.51,42.25 ; 88.47,71.15 J7.4 ; J7.4 89.92,69.7 ; J7.4 89.92,72.59 ; J7.4 91.36,71.15 ; XP3.6 34.42,38.15 ; XP3.6 35.61,36.96 ; XP3.6 34.42,35.76 ; XP3.6 33.22,36.96 ; 69.22,88.01 69.22,89.46 ; 69.22,88.01 67.77,88.01 ; 69.22,88.01 70.66,88.01 ; 69.22,88.01 69.22,86.56 ; J17.DG7 9.51,38.25 ; J17.DG7 9.51,36.25 ; J17.DG7 10.51,37.25 ; 5.01,26.25 J17.BG3 5.01,28.25 ; J18.DG7 9.51,64.29 ; J18.DG7 10.51,63.29 ; J18.DG7 9.51,62.28 ; 65.74,30.78 J9.5 ; J9.5 65.74,33.68 ; J9.5 64.29,32.23 ; J9.5 67.18,32.23 ; 5.01,64.29 J18.BG7 5.01,62.28 ; 5.01,71.79 J18.BG10 5.01,69.78 ; P6.1 109.73,105.83 ; P6.1 109.73,102.55 ; P6.1 111.37,104.19 ; P6.1 108.09,104.19 ; P6.2 96.07,104.19 ; P6.2 94.43,105.83 ; P6.2 94.43,102.55 ; P6.2 92.79,104.19 ; 9.51,28.75 J17.DG4 ; J17.DG4 9.51,30.75 ; J17.DG4 10.51,29.75 ; 108.97,84.21 TP4.1 ; TP4.1 108.97,87.24 ; TP4.1 107.45,85.72 ; TP4.1 110.48,85.72 ; 5.01,52.28 J18.BG3 5.01,54.29 ; J9.2 67.18,37.31 ; J9.2 65.74,38.76 ; J9.2 64.29,37.31 ; J9.2 65.74,35.86 ; J18.DG8 10.51,65.79 ; J18.DG8 9.51,66.79 ; J18.DG8 9.51,64.78 ; J9.4 70.82,33.68 ; J9.4 70.82,30.78 ; J9.4 69.37,32.23 ; J9.4 72.26,32.23 ; 69.22,91.64 69.22,93.09 ; 69.22,93.09 67.77,93.09 ; 69.22,93.09 69.22,94.54 ; 69.22,93.09 70.66,93.09 ; 5.01,61.79 J18.BG6 5.01,59.78 ; 5.01,64.78 J18.BG8 5.01,66.79 ; 9.51,67.28 J18.DG9 ; J18.DG9 9.51,69.29 ; J18.DG9 10.51,68.29 ; 5.01,28.75 J17.BG4 5.01,30.75 ; J17.DG2 10.51,24.75 ; J17.DG2 9.51,23.75 ; J17.DG2 9.51,25.75 ; 27.43,90.69 TP10.1 ; TP10.1 27.43,93.71 ; TP10.1 28.94,92.2 ; TP10.1 25.92,92.2 ; 5.01,45.75 J17.BG10 5.01,43.75 ; J7.2 86.28,76.23 ; J7.2 84.84,74.78 ; J7.2 83.39,76.23 ; J7.2 84.84,77.67 ; J18.DG3 9.51,54.29 ; J18.DG3 9.51,52.28 ; J18.DG3 10.51,53.29 ; J18.DG5 9.51,59.29 ; J18.DG5 9.51,57.28 ; J18.DG5 10.51,58.29 ; 5.01,38.25 J17.BG7 5.01,36.25 ; 5.01,31.25 J17.BG5 5.01,33.25 ; 5.01,23.75 J17.BG2 5.01,25.75 ; J18.DG4 9.51,56.79 ; J18.DG4 9.51,54.78 ; J18.DG4 10.51,55.79 ; 5.01,56.79 J18.BG4 5.01,54.78 ; 5.01,23.25 J17.BG1 5.01,21.25 ; J17.DG5 10.51,32.25 ; J17.DG5 9.51,33.25 ; J17.DG5 9.51,31.25 ; J17.DG6 10.51,34.75 ; J17.DG6 9.51,35.75 ; J17.DG6 9.51,33.75 ; 5.01,33.75 J17.BG6 5.01,35.75 ; 5.01,49.78 J18.BG2 5.01,51.79
  L5GND w0.508: 89.48,30.78 J8.4 ; J8.4 88.04,32.23 ; J8.4 90.93,32.23 ; J8.4 89.48,33.68 ; 13.84,90.69 TP6.1 ; TP6.1 15.35,92.2 ; TP6.1 13.84,93.71 ; TP6.1 12.33,92.2 ; J17.DG7 9.51,38.25 ; J17.DG7 9.51,36.25 ; J17.DG7 10.51,37.25 ; J17.DG3 9.51,28.25 ; J17.DG3 10.51,27.25 ; J17.DG3 9.51,26.25 ; 5.01,40.75 J17.BG8 5.01,38.75 ; 33.06,5.49 XP1.6 ; XP1.6 34.32,6.74 ; XP1.6 34.32,4.23 ; XP1.6 35.57,5.49 ; 69.22,93.09 69.22,94.54 ; 69.22,93.09 67.77,93.09 ; 69.22,93.09 70.66,93.09 ; 69.22,93.09 69.22,91.64 ; J7.2 86.28,76.23 ; J7.2 84.84,77.67 ; J7.2 84.84,74.78 ; J7.2 83.39,76.23 ; 9.51,64.78 J18.DG8 ; J18.DG8 10.51,65.79 ; J18.DG8 9.51,66.79 ; J17.DG5 9.51,33.25 ; J17.DG5 10.51,32.25 ; J17.DG5 9.51,31.25 ; 89.92,74.78 J7.3 ; J7.3 91.36,76.23 ; J7.3 88.47,76.23 ; J7.3 89.92,77.67 ; J9.5 65.74,33.68 ; J9.5 67.18,32.23 ; J9.5 65.74,30.78 ; J9.5 64.29,32.23 ; 74.3,86.56 J1.4 ; J1.4 72.85,88.01 ; J1.4 74.3,89.46 ; J1.4 75.74,88.01 ; 25.92,92.2 TP10.1 ; TP10.1 27.43,90.69 ; TP10.1 27.43,93.71 ; TP10.1 28.94,92.2 ; J9.4 70.82,33.68 ; J9.4 69.37,32.23 ; J9.4 70.82,30.78 ; J9.4 72.26,32.23 ; 69.22,88.01 70.66,88.01 ; 69.22,88.01 67.77,88.01 ; 69.22,88.01 69.22,86.56 ; 69.22,88.01 69.22,89.46 ; J8.5 85.85,32.23 ; J8.5 84.4,33.68 ; J8.5 82.96,32.23 ; J8.5 84.4,30.78 ; 69.37,37.31 J9.3 ; J9.3 72.26,37.31 ; J9.3 70.82,35.86 ; J9.3 70.82,38.76 ; J5.3 71.3,77.72 ; J5.3 72.75,76.28 ; J5.3 71.3,74.83 ; J5.3 69.85,76.28 ; 9.51,41.25 J17.DG9 ; J17.DG9 9.51,43.25 ; J17.DG9 10.51,42.25 ; 5.01,64.78 J18.BG8 5.01,66.79 ; 40.02,92.08 TP12.1 ; TP12.1 41.53,93.59 ; TP12.1 43.04,92.08 ; TP12.1 41.53,90.56 ; 5.01,61.79 J18.BG6 5.01,59.78 ; 5.01,69.29 J18.BG9 5.01,67.28 ; 5.01,51.79 J18.BG2 5.01,49.78 ; J8.3 89.48,38.76 ; J8.3 90.93,37.31 ; J8.3 88.04,37.31 ; J8.3 89.48,35.86 ; J5.5 67.67,71.2 ; J5.5 66.22,69.75 ; J5.5 66.22,72.64 ; J5.5 64.77,71.2 ; P6.2 94.43,105.83 ; P6.2 94.43,102.55 ; P6.2 96.07,104.19 ; P6.2 92.79,104.19 ; J18.DG3 9.51,54.29 ; J18.DG3 10.51,53.29 ; J18.DG3 9.51,52.28 ; 5.01,28.25 J17.BG3 5.01,26.25 ; TP4.1 108.97,87.24 ; TP4.1 110.48,85.72 ; TP4.1 107.45,85.72 ; TP4.1 108.97,84.21 ; 9.51,62.28 J18.DG7 ; J18.DG7 10.51,63.29 ; J18.DG7 9.51,64.29 ; 9.51,43.75 J17.DG10 ; J17.DG10 10.51,44.75 ; J17.DG10 9.51,45.75 ; J18.DG4 9.51,56.79 ; J18.DG4 9.51,54.78 ; J18.DG4 10.51,55.79 ; J17.DG8 9.51,40.75 ; J17.DG8 10.51,39.75 ; J17.DG8 9.51,38.75 ; XP3.6 35.61,36.96 ; XP3.6 34.42,38.15 ; XP3.6 33.22,36.96 ; XP3.6 34.42,35.76 ; 5.01,31.25 J17.BG5 5.01,33.25 ; 64.77,76.28 J5.2 ; J5.2 66.22,74.83 ; J5.2 67.67,76.28 ; J5.2 66.22,77.72 ; 83.39,71.15 J7.5 ; J7.5 84.84,72.59 ; J7.5 84.84,69.7 ; J7.5 86.28,71.15 ; TP13.1 37.72,109.97 ; TP13.1 36.21,108.46 ; TP13.1 39.23,108.46 ; TP13.1 37.72,106.95 ; 9.51,67.28 J18.DG9 ; J18.DG9 9.51,69.29 ; J18.DG9 10.51,68.29 ; 9.51,69.78 J18.DG10 ; J18.DG10 9.51,71.79 ; J18.DG10 10.51,70.79 ; 72.85,93.09 J1.3 ; J1.3 74.3,94.54 ; J1.3 74.3,91.64 ; J1.3 75.74,93.09 ; 5.01,35.75 J17.BG6 5.01,33.75 ; 5.01,45.75 J17.BG10 5.01,43.75 ; 9.51,28.75 J17.DG4 ; J17.DG4 9.51,30.75 ; J17.DG4 10.51,29.75 ; J18.DG2 9.51,51.79 ; J18.DG2 9.51,49.78 ; J18.DG2 10.51,50.79 ; 5.01,64.29 J18.BG7 5.01,62.28 ; J17.DG6 9.51,35.75 ; J17.DG6 10.51,34.75 ; J17.DG6 9.51,33.75 ; 5.01,49.29 J18.BG1 5.01,47.28 ; 5.01,69.78 J18.BG10 5.01,71.79 ; 5.01,59.29 J18.BG5 5.01,57.28 ; J8.2 84.4,38.76 ; J8.2 82.96,37.31 ; J8.2 85.85,37.31 ; J8.2 84.4,35.86 ; J18.DG5 9.51,59.29 ; J18.DG5 9.51,57.28 ; J18.DG5 10.51,58.29 ; 109.73,102.55 P6.1 ; P6.1 111.37,104.19 ; P6.1 108.09,104.19 ; P6.1 109.73,105.83 ; 5.01,28.75 J17.BG4 5.01,30.75 ; 89.92,69.7 J7.4 ; J7.4 88.47,71.15 ; J7.4 91.36,71.15 ; J7.4 89.92,72.59 ; 9.51,21.25 J17.DG1 ; J17.DG1 10.51,22.25 ; J17.DG1 9.51,23.25 ; 5.01,41.25 J17.BG9 5.01,43.25 ; 5.01,38.25 J17.BG7 5.01,36.25 ; 92.33,84.34 TP8.1 ; TP8.1 90.82,85.85 ; TP8.1 92.33,87.36 ; TP8.1 93.84,85.85 ; J18.DG6 10.51,60.79 ; J18.DG6 9.51,59.78 ; J18.DG6 9.51,61.79 ; J9.2 67.18,37.31 ; J9.2 64.29,37.31 ; J9.2 65.74,38.76 ; J9.2 65.74,35.86 ; 5.01,21.25 J17.BG1 5.01,23.25 ; J5.4 71.3,72.64 ; J5.4 69.85,71.2 ; J5.4 71.3,69.75 ; J5.4 72.75,71.2 ; J17.DG2 9.51,25.75 ; J17.DG2 9.51,23.75 ; J17.DG2 10.51,24.75 ; 5.01,25.75 J17.BG2 5.01,23.75 ; 5.01,56.79 J18.BG4 5.01,54.78 ; 5.01,52.28 J18.BG3 5.01,54.29 ; 9.51,47.28 J18.DG1 ; J18.DG1 10.51,48.29 ; J18.DG1 9.51,49.29
  BOTTOM w0.279: U3.13 20.22,44.83 v1(20.45,44.83)
  BOTTOM w0.508: C70.2 v1(51.82,62.1) ; C66.2 v1(44.45,51.31) ; v1(45.59,51.43) 45.85,51.69 C71.2 ; J2.2 v1(108.27,72.07) ; C4.2 v1(24.89,43.81) ; XC58.1 v1(48.89,26.92) ; C68.2 v1(56.52,63.25) ; XC11.1 v1(43.05,32.38) ; C23.2 v1(51.18,68.96) ; v2(56.26,50.92) 55.88,50.54 C86.2 ; C77.2 v1(53.34,42.04) ; C2.2 v1(25.15,49.78) ; C63.2 v1(42.8,51.18) ; L2.1 v1(96.27,59.94) ; C25.2 v1(51.56,65.15) ; v1(53.34,45.09) 53.34,45.59 ; XC12.2 v1(40.77,32.64) ; L1.1 v1(96.27,47.37) ; C24.2 v1(59.44,67.18) ; R36.1 v1(66.17,54.23) ; C85.2 56.06,55.42 v2(55.84,55.42) ; J6.2 v1(108.71,58.23) ; R11.2 v1(51.05,67.18) ; R21.1 v1(57.3,43.71) ; R33.1 v1(66.17,53.34) ; C6.2 v1(24.89,41.66) ; C14.2 v1(52.32,77.22) ; v1(59.83,59.67) 59.82,59.65 C87.2 ; R34.1 v1(66.17,61.59) ; J2.4 v1(108.14,80.84) ; C103.2 v1(53.47,64.77) ; C91.1 v1(59.64,43.43) ; R44.1 v1(66.17,46.1) ; XC57.2 v1(49.15,24.89) ; C90.2 v1(59.44,48.51) ; J6.4 v1(108.84,49.47) ; C3.2 v1(25.02,47.75)
  vias: v1(2.54,88.14) v1(2.92,78.11) v1(3.68,81.03) v1(4.83,17.65) v1(5.21,8.38) v1(5.71,13.97) v1(8,80.52) v1(8.13,76.71) v1(8.76,88.27) v1(9.14,11.3) v1(10.29,2.79) v1(11.43,7.62) v1(11.56,14.61) v1(12.95,19.05) v1(14.35,76.96) v1(15.24,74.17) v1(15.75,4.44) v1(16,11.56) v1(16.64,87.12) v1(17.53,83.95) v1(17.65,15.62) v1(18.03,19.3) v1(18.8,89.15) v1(19.05,15.88) v1(21.21,12.83) v1(21.46,87.38) v1(21.72,78.11) v1(22.23,20.45) v1(22.99,25.27) v1(23.75,29.08) v1(24.89,86.74) v1(25.4,75.18) v1(26.16,17.4) v1(26.29,78.99) v1(27.94,26.54) v1(31.37,23.62) v1(32.51,85.34) v1(43.43,1.91) v1(43.94,75.18) v1(44.2,71.5) v1(45.21,82.17) v1(46.35,104.65) v1(48.01,104.52) v1(49.53,104.14) v1(50.29,3.43) v1(52.58,7.49) v1(55.75,6.73) v1(55.88,2.92) v1(58.17,11.56) v1(59.69,17.78) v1(59.94,6.6) v1(60.71,61.21) v1(61.85,62.23) v1(62.36,65.53) v1(62.61,3.43) v1(63.25,68.2) v1(63.37,17.02) v1(63.63,9.53) v1(64.14,62.23) v1(66.29,66.8) v1(66.55,64.64) v1(66.8,7.37) v1(67.69,44.7) v1(69.09,61.98) v1(69.34,45.34) v1(70.48,67.31) v1(70.61,64.64) v1(70.87,61.21) v1(70.87,46.35) v1(72.14,53.98) v1(72.14,11.18) v1(72.39,8) v1(72.77,46.61) v1(73.03,61.21) v1(73.33,62.23) v1(73.53,53.98) v1(74.3,46.48) v1(74.42,82.8) v1(74.42,78.74) v1(74.68,14.48) v1(74.93,53.98) v1(75.06,10.92) v1(75.18,25.78) v1(75.56,21.46) v1(76.07,7.11) v1(76.33,53.98) v1(77.47,28.7) v1(77.72,77.6) v1(77.85,53.98) v1(79.5,53.98) v1(82.3,25.27) v1(82.6,63.75) v1(83.06,27.94) v1(84.45,53.85) v1(84.45,45.34) v1(84.84,61.85) v1(85.85,46.35) v1(85.98,53.85) v1(86.03,61.47) v1(86.16,55.88) v1(86.61,26.03) v1(87.38,65.79) v1(87.38,53.72) v1(87.63,61.34) v1(87.63,46.48) v1(88.77,53.72) v1(88.9,60.58) v1(89.15,52.07) v1(89.28,28.07) v1(89.41,46.48) v1(89.66,55.63) v1(89.79,59.82) v1(90.42,47.75) v1(90.81,64.52) v1(90.81,62.61) v1(90.81,60.71) v1(91.06,24.77) v1(91.44,66.93) v1(91.82,41.02) v1(92.51,51.43) v1(92.58,47.88) v1(92.71,68.2) v1(92.71,64.52) v1(92.71,62.61) v1(92.71,60.71) v1(93.34,65.79) v1(93.98,69.47) v1(93.98,47.88) v1(94.23,27.43) v1(94.62,66.93) v1(94.74,36.83) v1(94.74,31.37) v1(95.25,70.74) v1(95.38,42.42) v1(95.5,68.07) v1(96.52,71.88) v1(96.77,69.22) v1(96.9,25.91) v1(97.79,73.28) v1(97.79,70.36) v1(97.92,3.94) v1(98.42,38.61) v1(98.93,71.5) v1(99.06,74.42) v1(99.06,32.77) v1(99.69,46.35) v1(99.69,27.69) v1(100.08,41.91) v1(100.2,72.77) v1(100.33,75.82) v1(100.46,66.8) v1(100.46,29.84) v1(101.6,77.09) v1(101.98,5.08) v1(102.23,74.55) v1(102.74,23.5) v1(103.5,19.69) v1(103.63,16.76) v1(103.76,36.45) v1(103.76,26.67) v1(104.01,77.6) v1(104.01,75.18) v1(104.39,40.64) v1(104.39,30.35) v1(104.9,33.02) v1(105.03,14.1) v1(105.41,71.63) v1(105.41,52.96) v1(105.54,54.86) v1(105.92,68.45) v1(106.05,77.6) v1(106.05,75.18) v1(106.3,23.5) v1(106.3,16.76) v1(106.55,11.81) v1(106.81,64.13) v1(107.19,52.96) v1(107.31,54.86) v1(107.44,43.18) v1(107.44,30.73) v1(107.95,77.6) v1(107.95,75.18) v1(108.46,36.96) v1(108.84,54.86) v1(108.84,52.83) v1(110.74,28.83) v1(111,18.67) v1(111.38,41.15) v1(111.38,33.15) v1(111.63,23.24) v1(111.76,10.8) v1(113.41,37.46) v2(19.18,46.48) v2(39.5,27.94) v2(39.5,26.77) v2(39.47,16.46) v2(39.47,14.2) v2(40.51,27.94) v2(40.51,26.8) v2(40.82,16.46) v2(40.82,15.29) v2(40.82,14.2) v2(50.42,55.5) v2(50.42,54.23) v2(50.42,52.96) v2(50.42,51.69) v2(51.69,55.5) v2(51.69,54.23) v2(51.69,52.96) v2(51.69,51.69) v2(52.96,55.5) v2(52.96,54.23) v2(52.96,52.96) v2(52.96,51.69) v2(53.72,104.9) v2(53.72,103) v2(54.23,55.5) v2(54.23,54.23) v2(54.23,52.96) v2(54.23,51.69) v2(55.37,104.9) v2(55.5,103) v2(95.63,54.23) v2(95.63,53.21) v2(96.77,54.23) v2(96.77,53.21)
